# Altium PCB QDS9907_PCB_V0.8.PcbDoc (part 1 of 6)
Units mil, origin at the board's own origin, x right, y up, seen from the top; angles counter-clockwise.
Board outline 3410.03 x 4010.03 mil, 8 copper layers (Top Layer, GND1, INT1, INT2, PWR1, GND2, GND3, Bottom Layer), stack 81.668 mil thick; 250 components, 129 nets, 7010 pads, 701 vias.
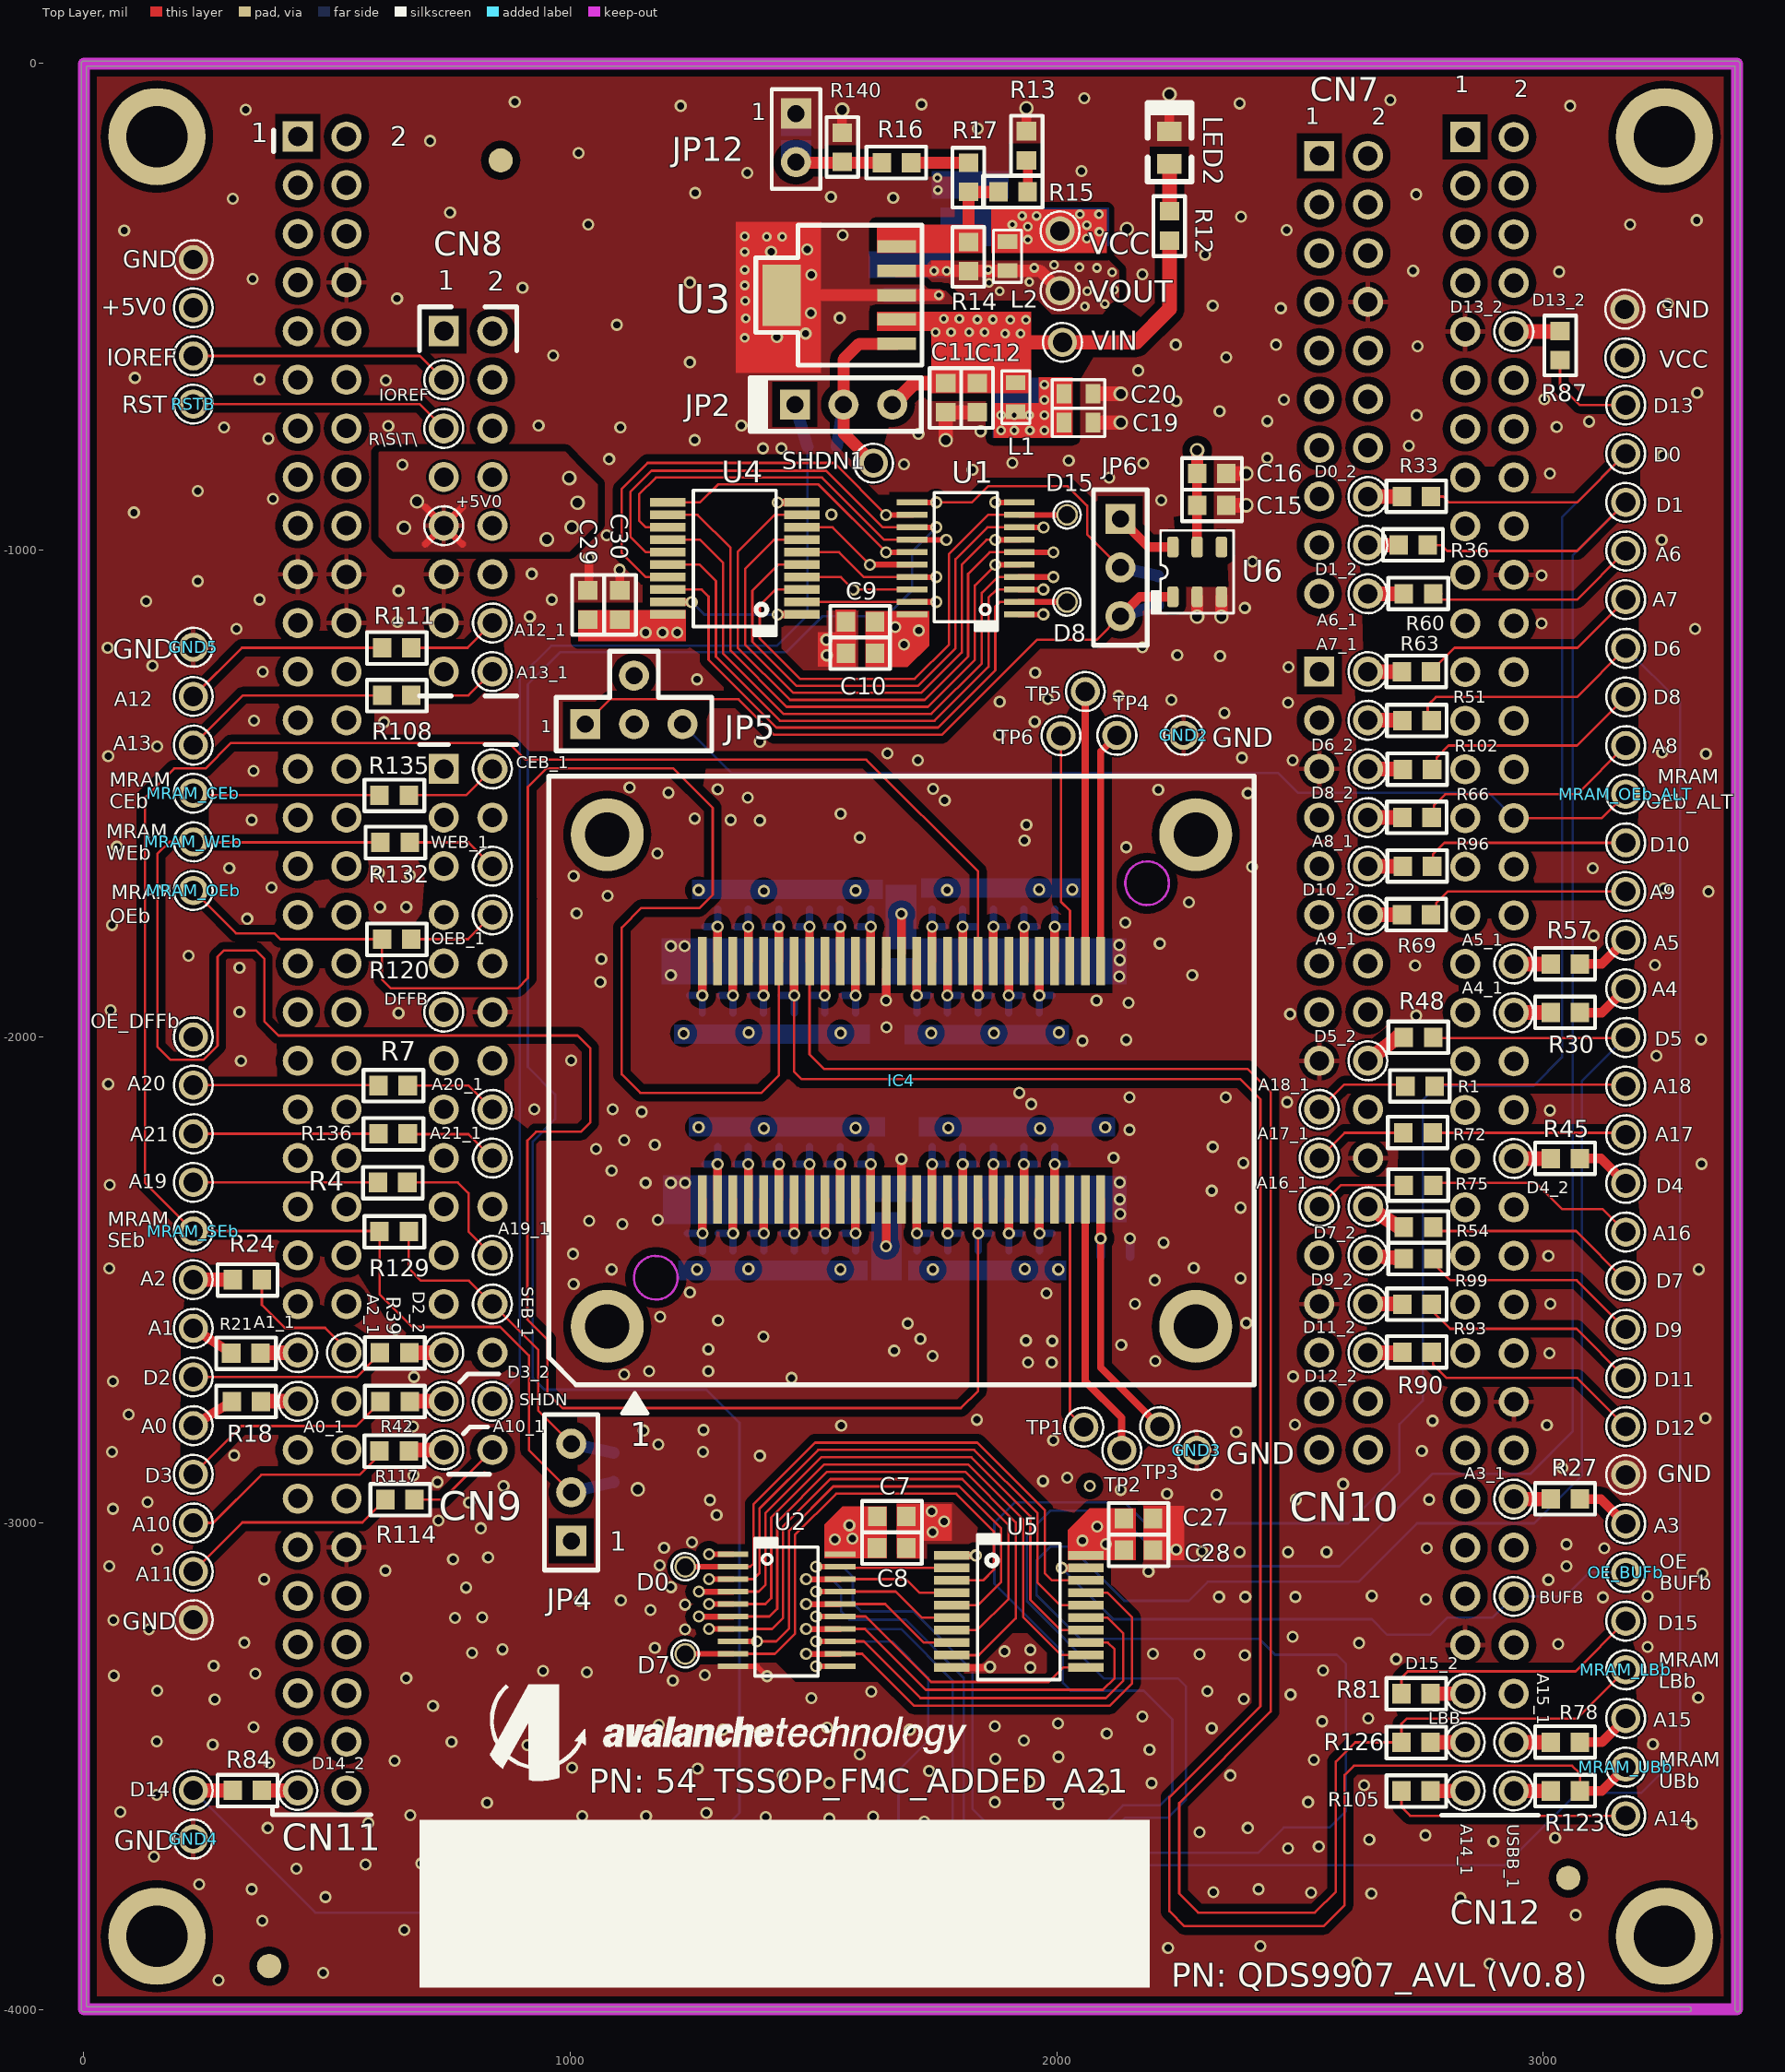
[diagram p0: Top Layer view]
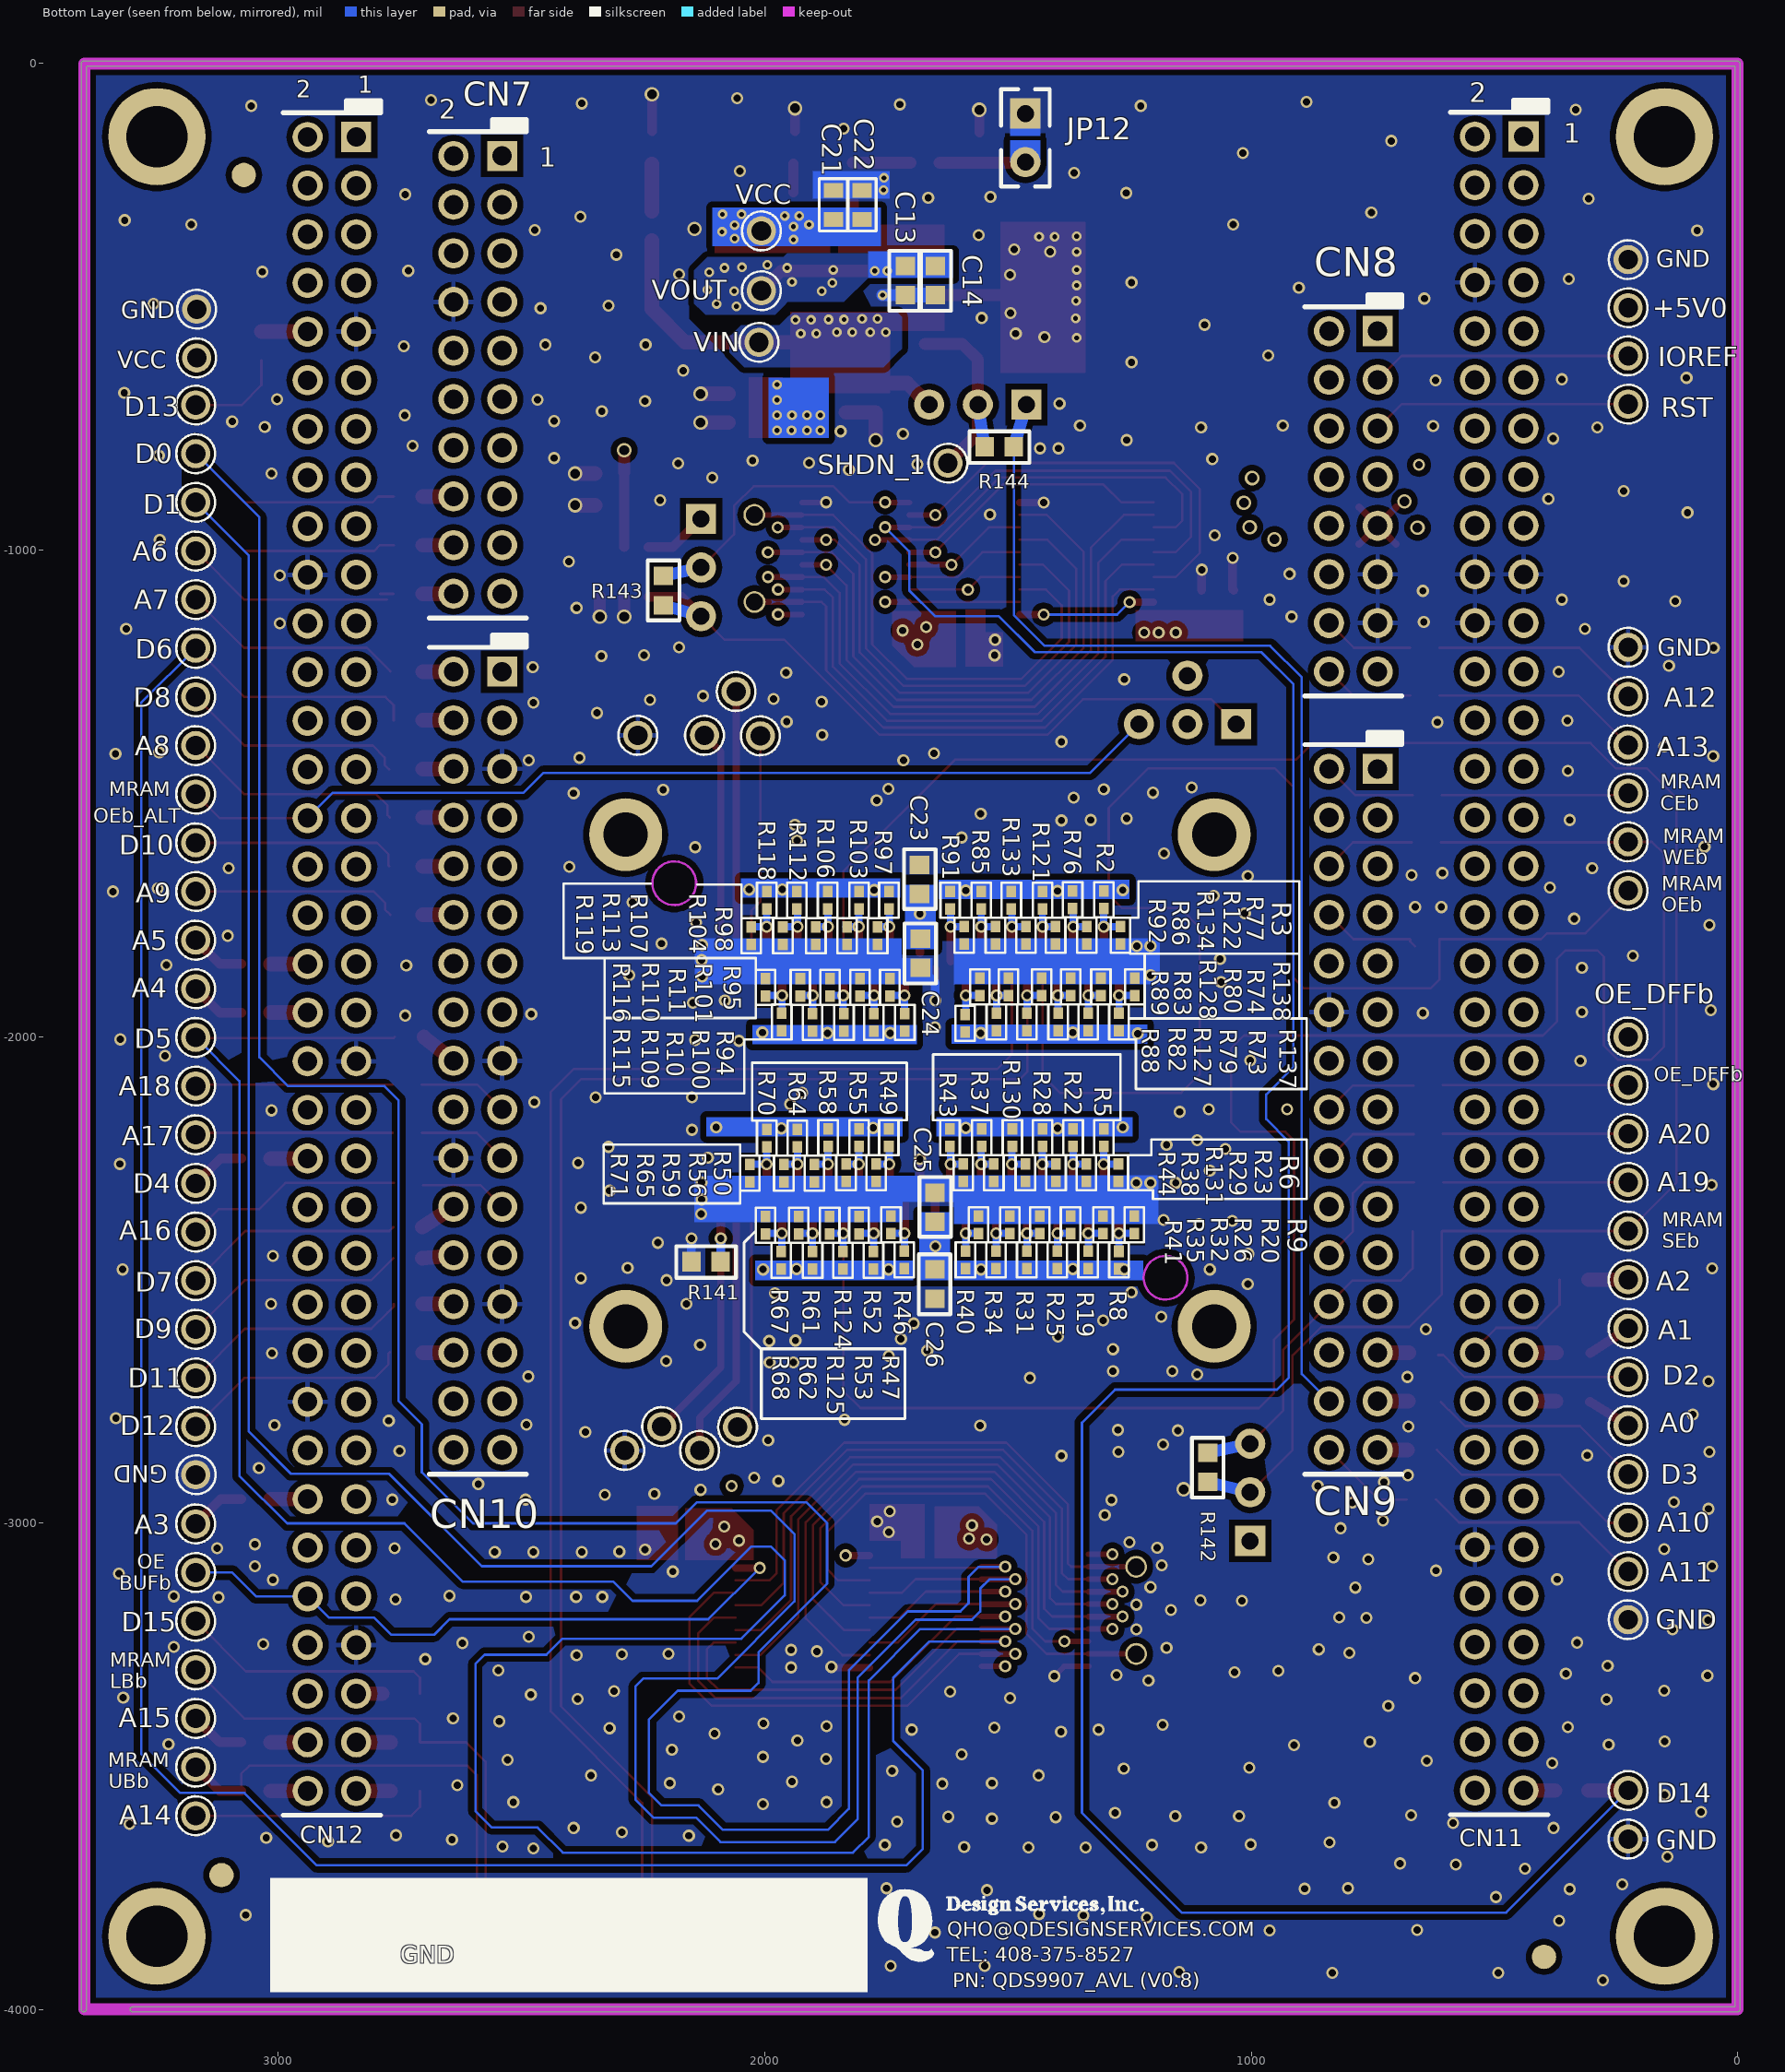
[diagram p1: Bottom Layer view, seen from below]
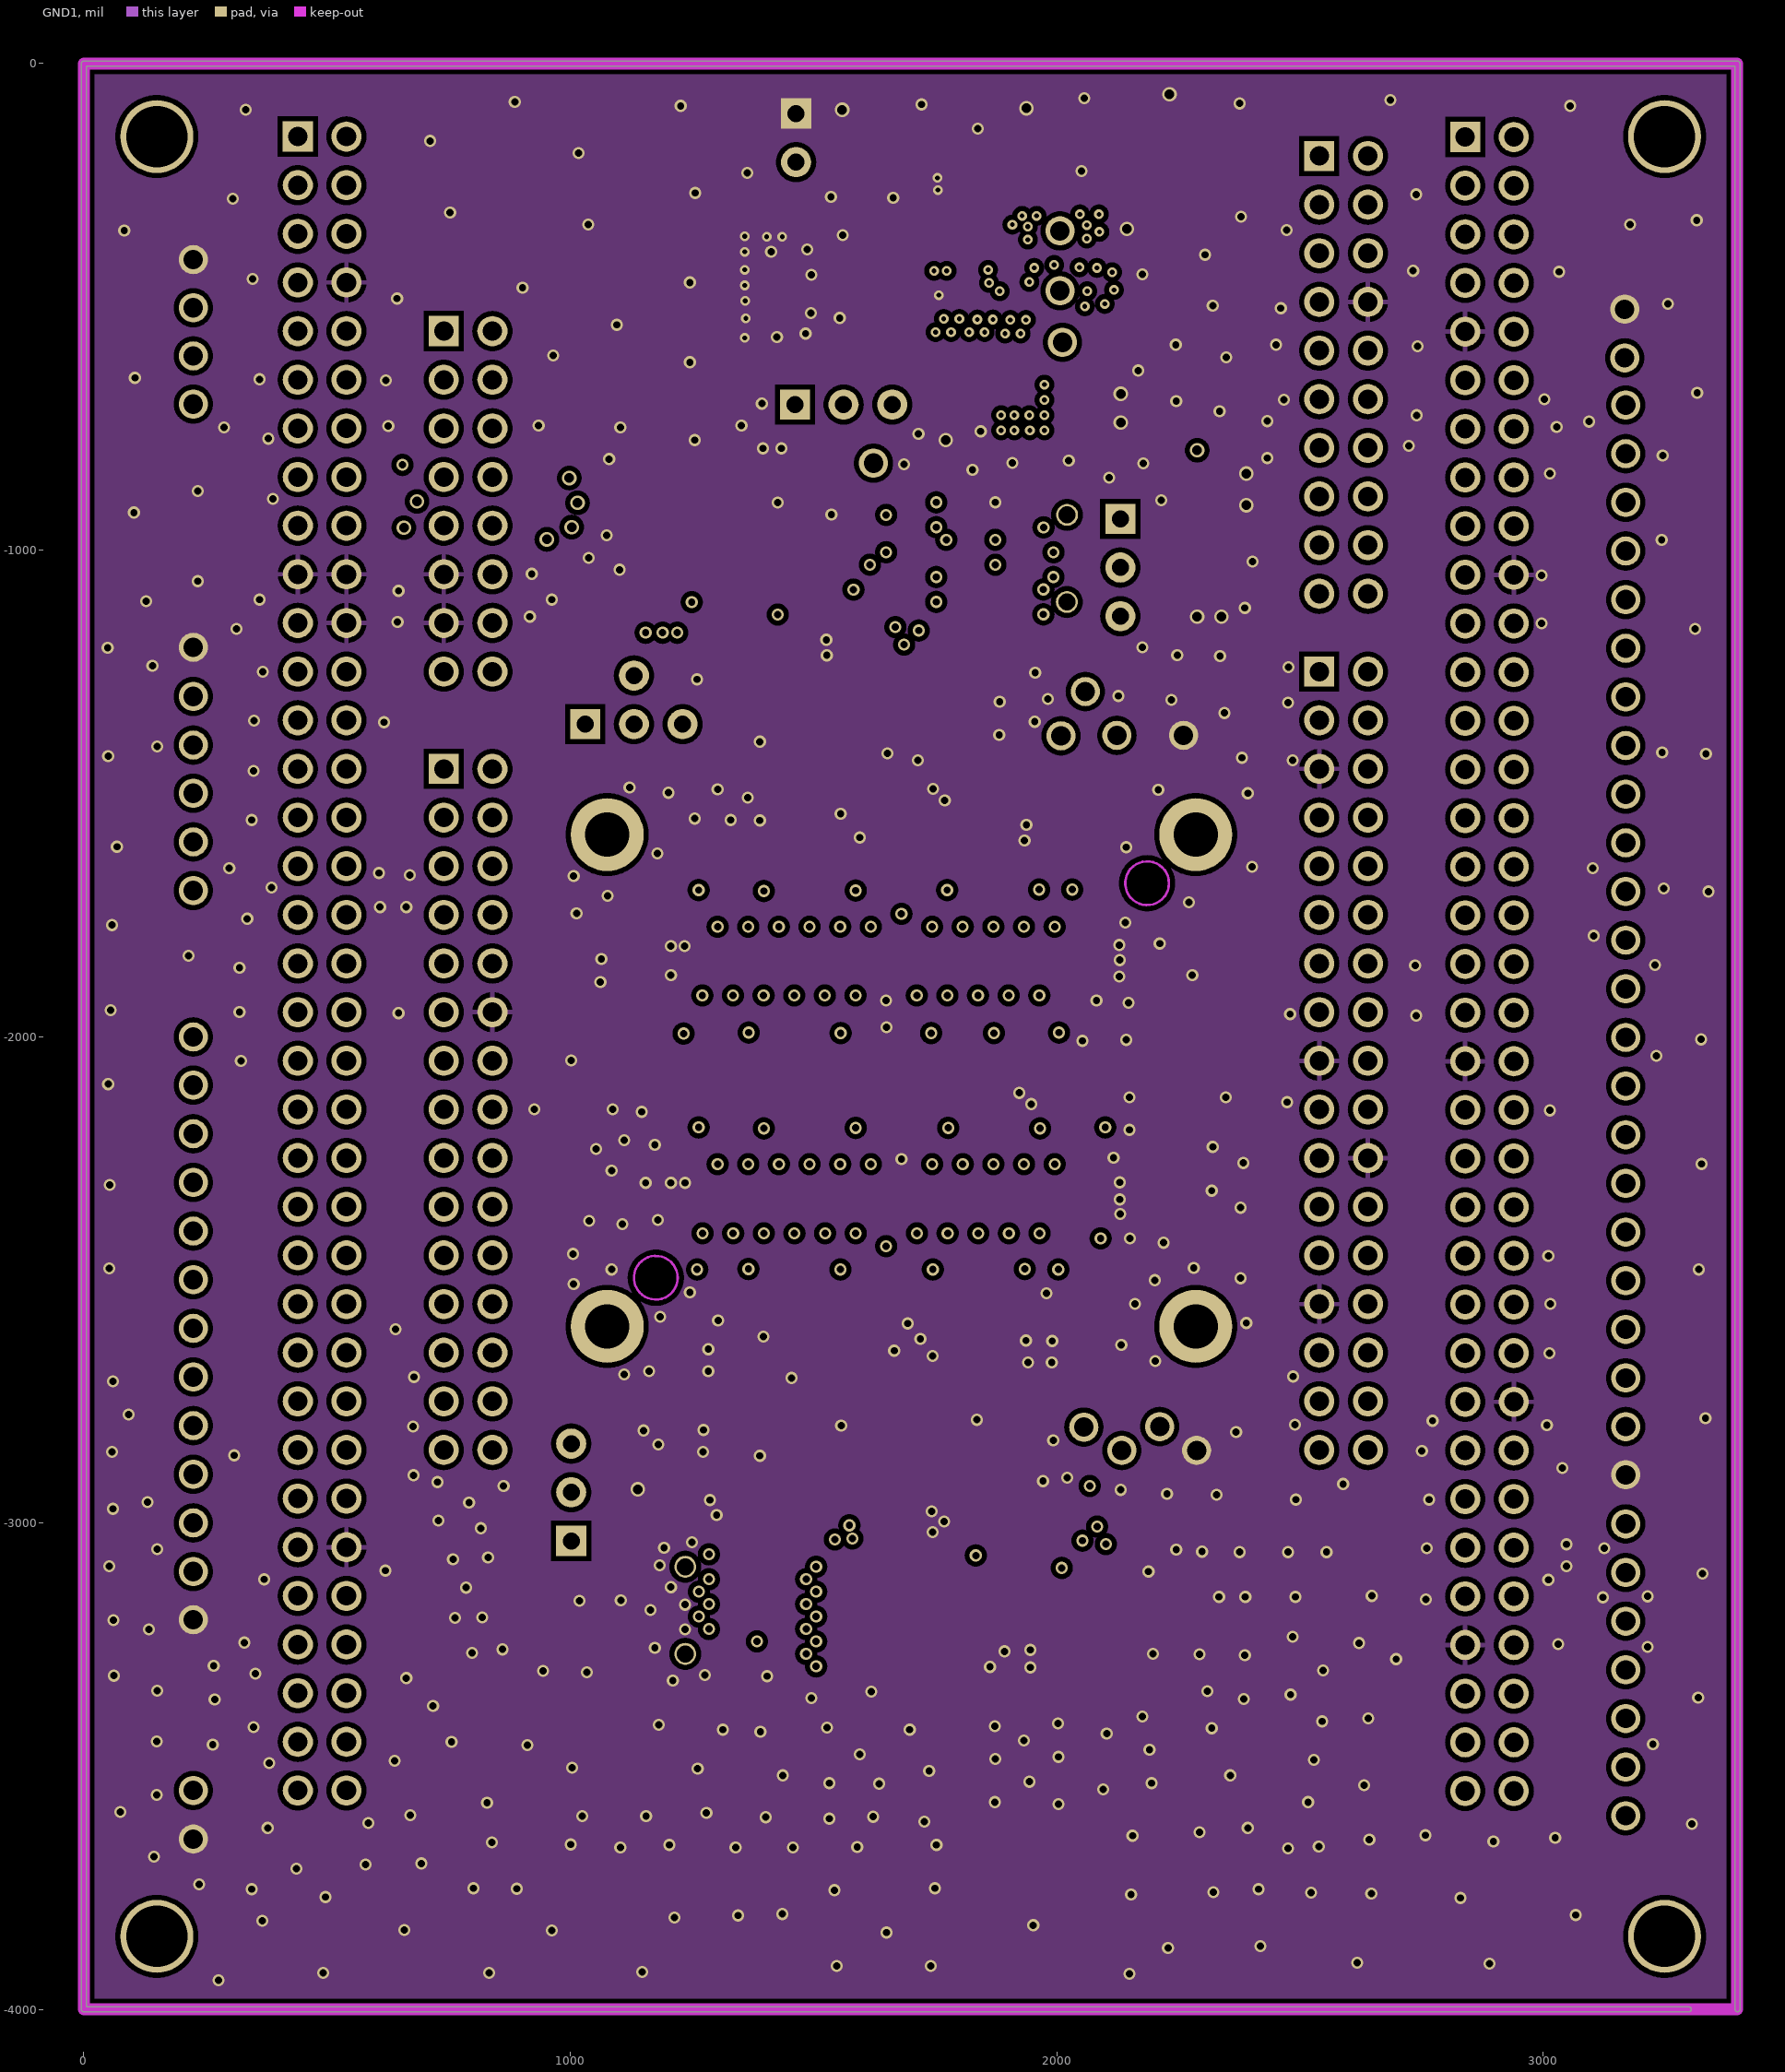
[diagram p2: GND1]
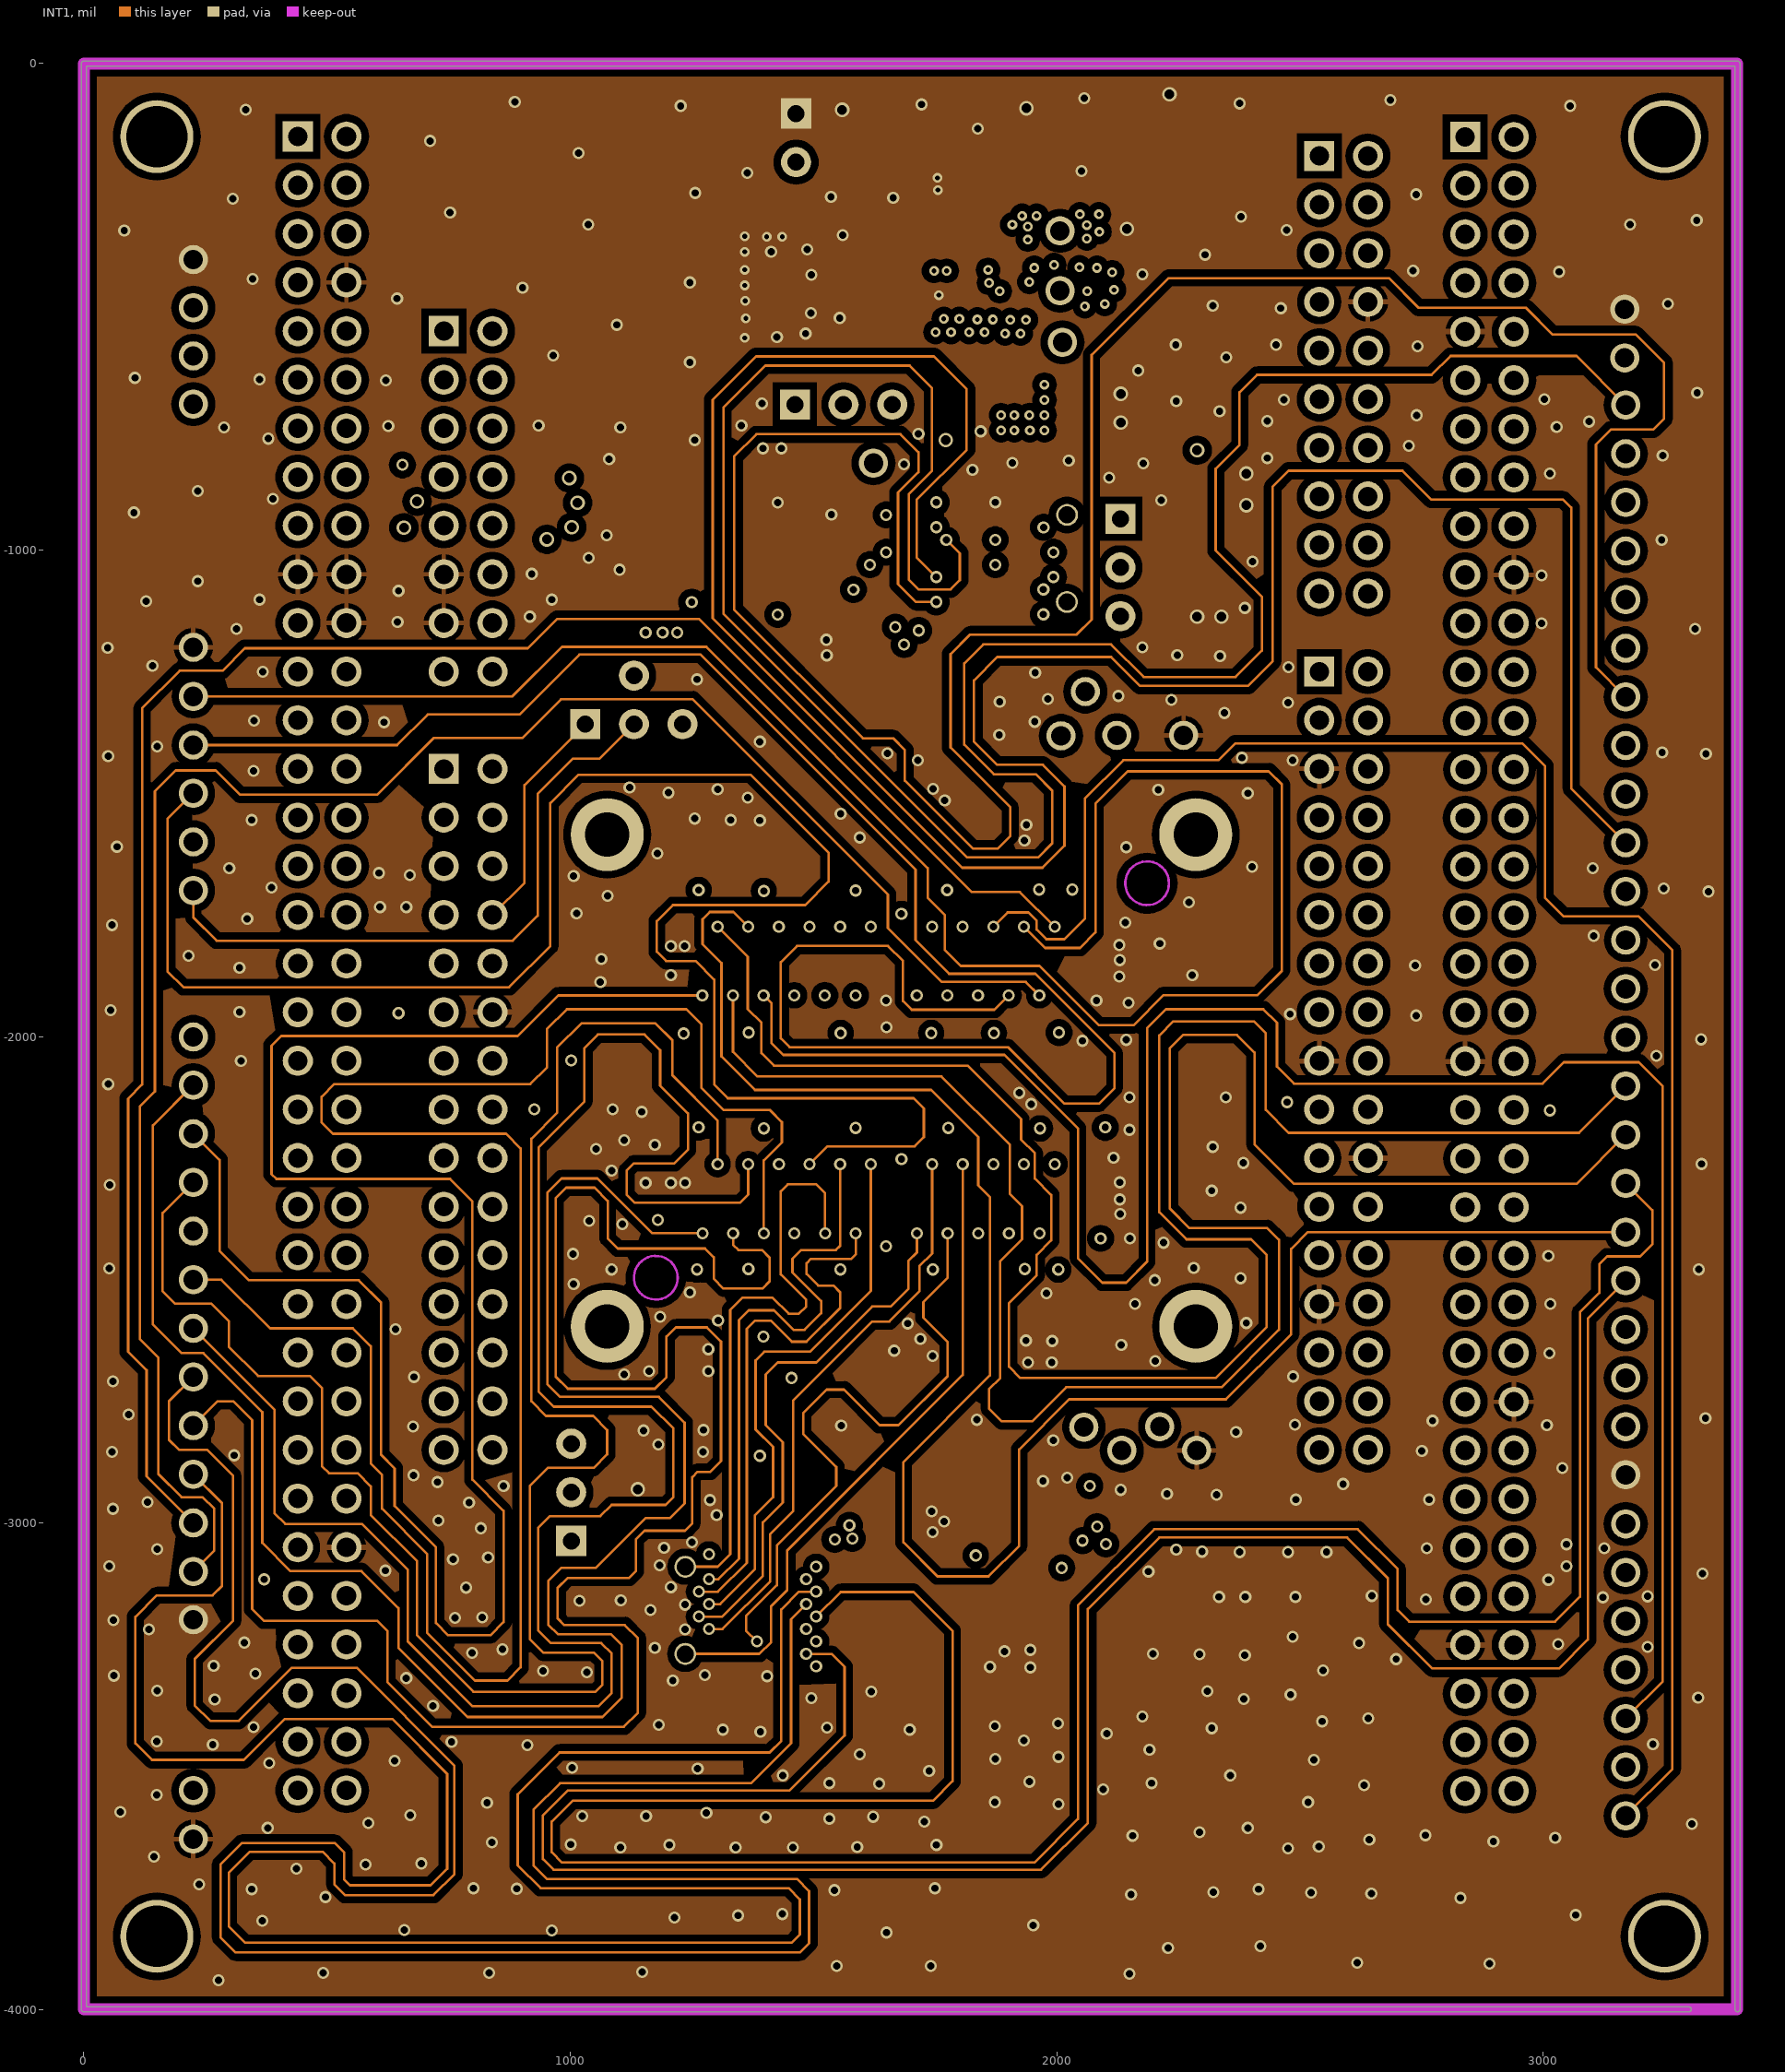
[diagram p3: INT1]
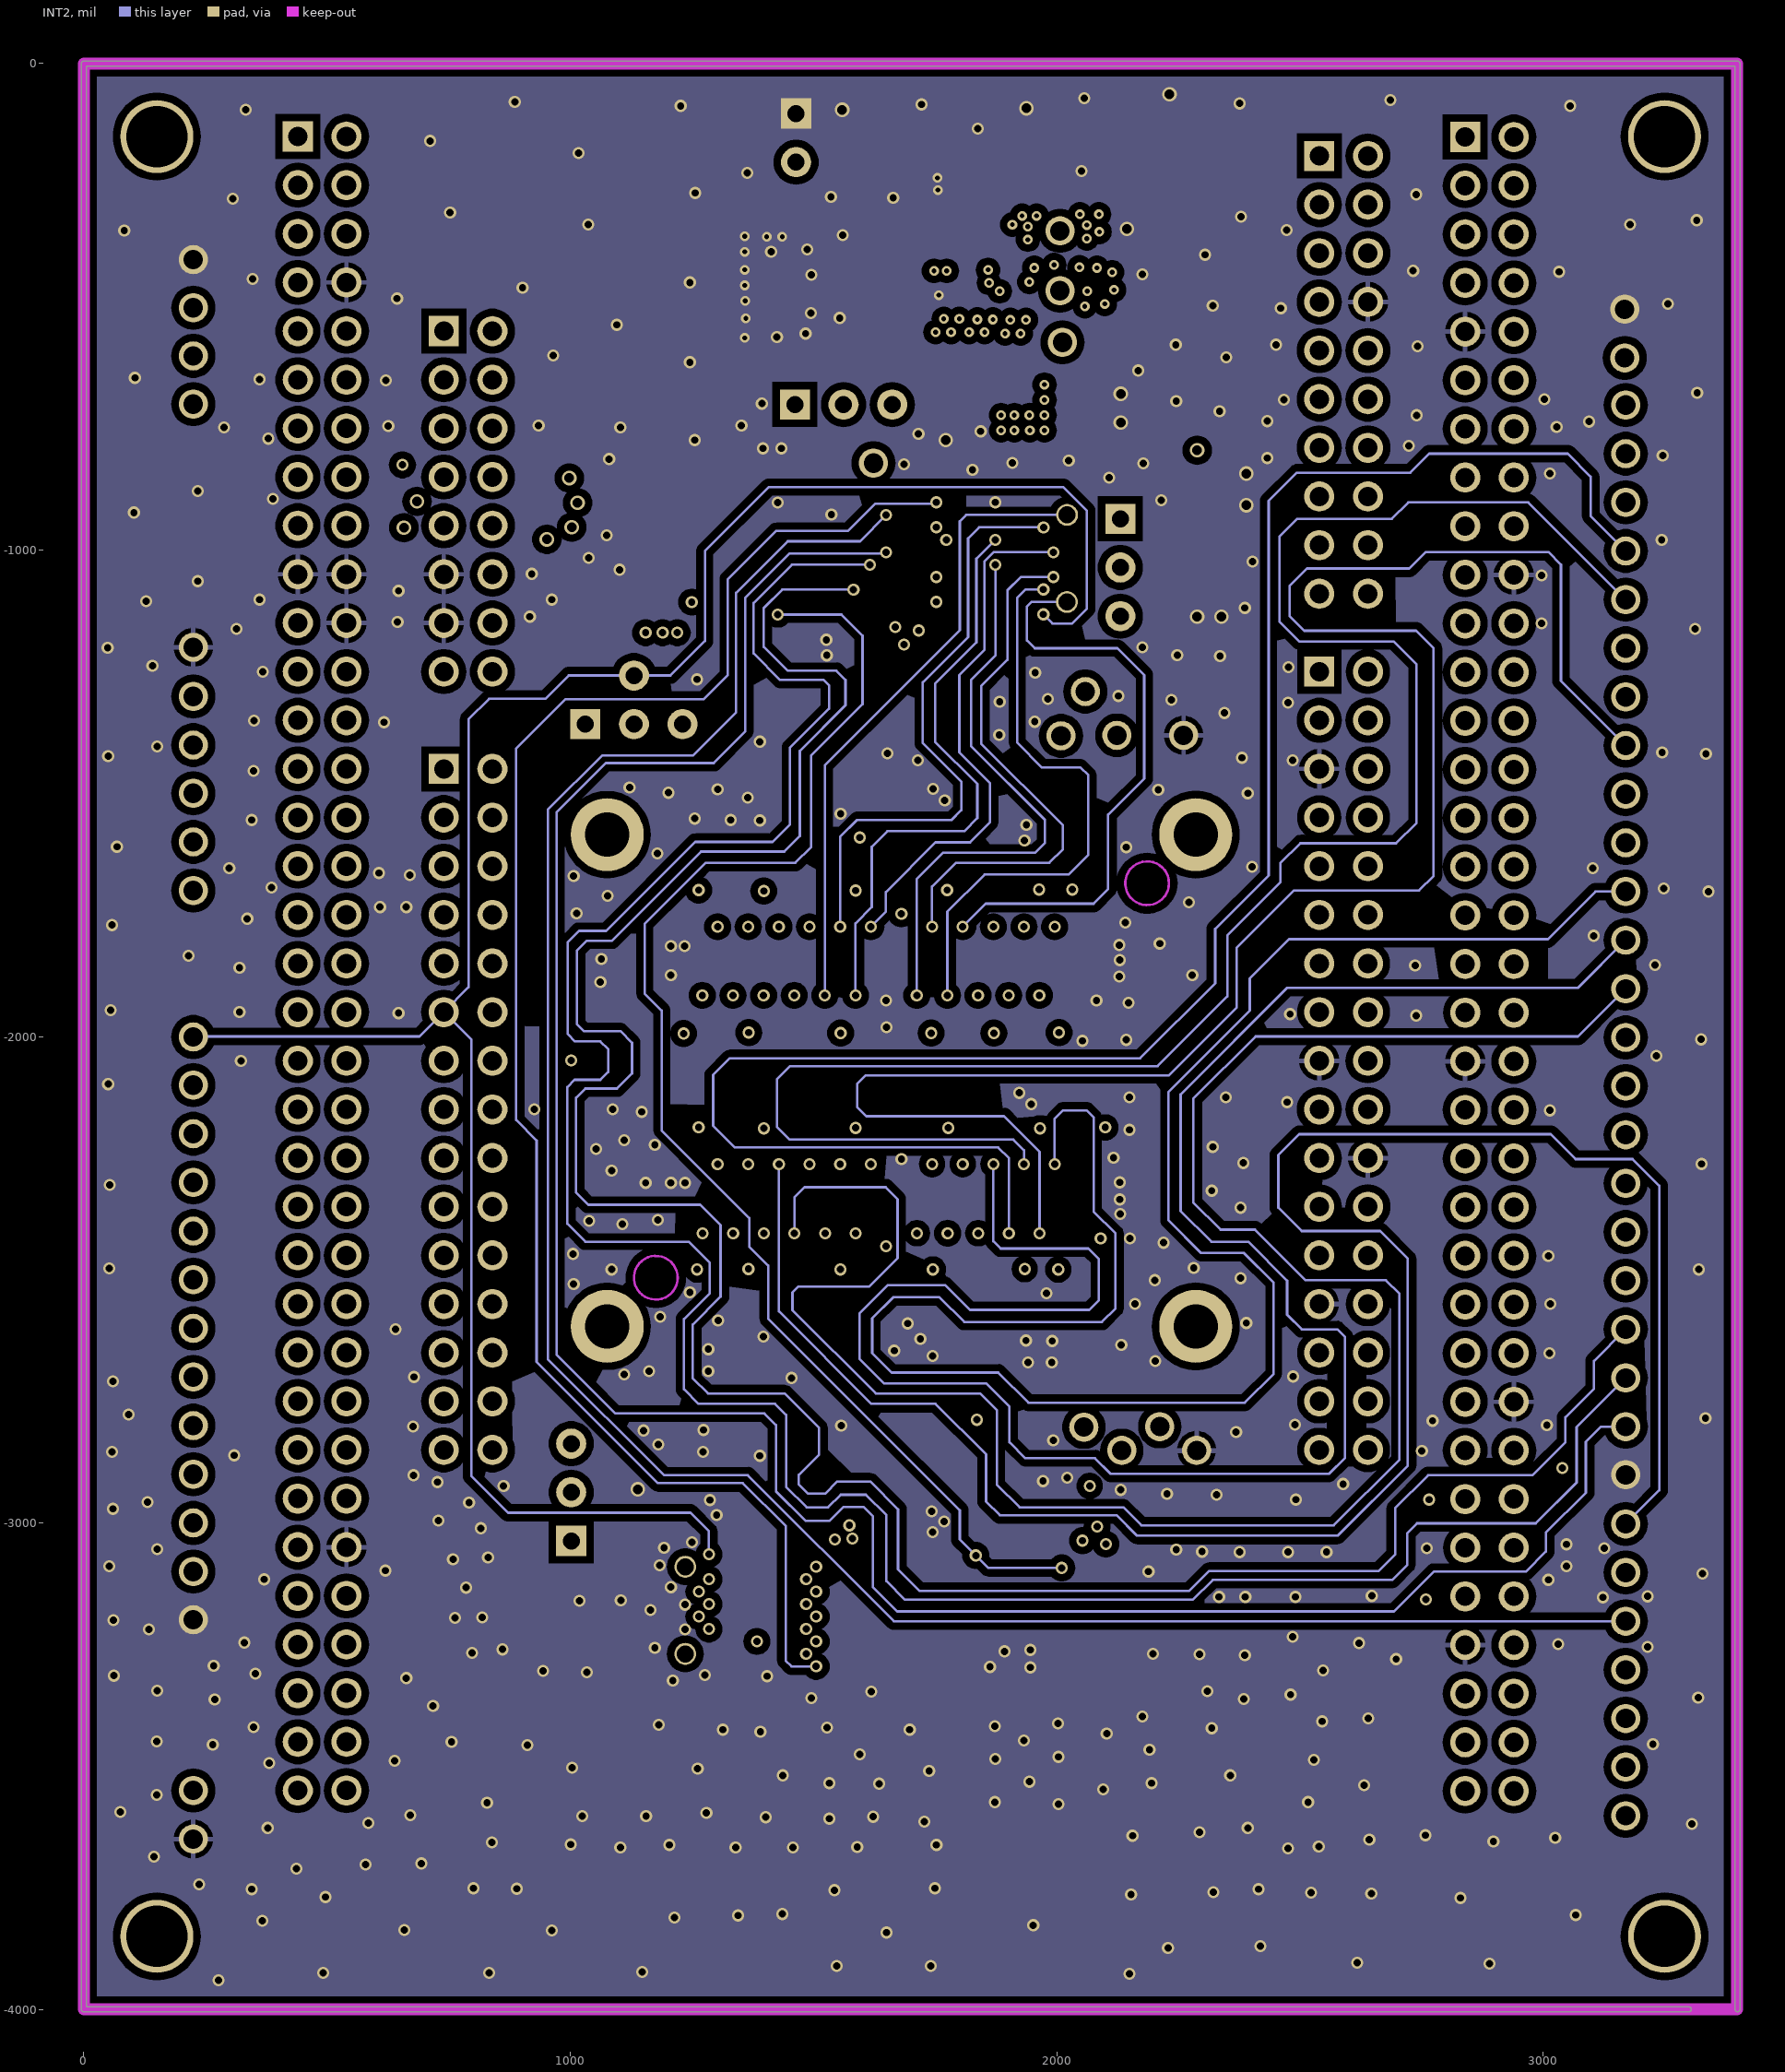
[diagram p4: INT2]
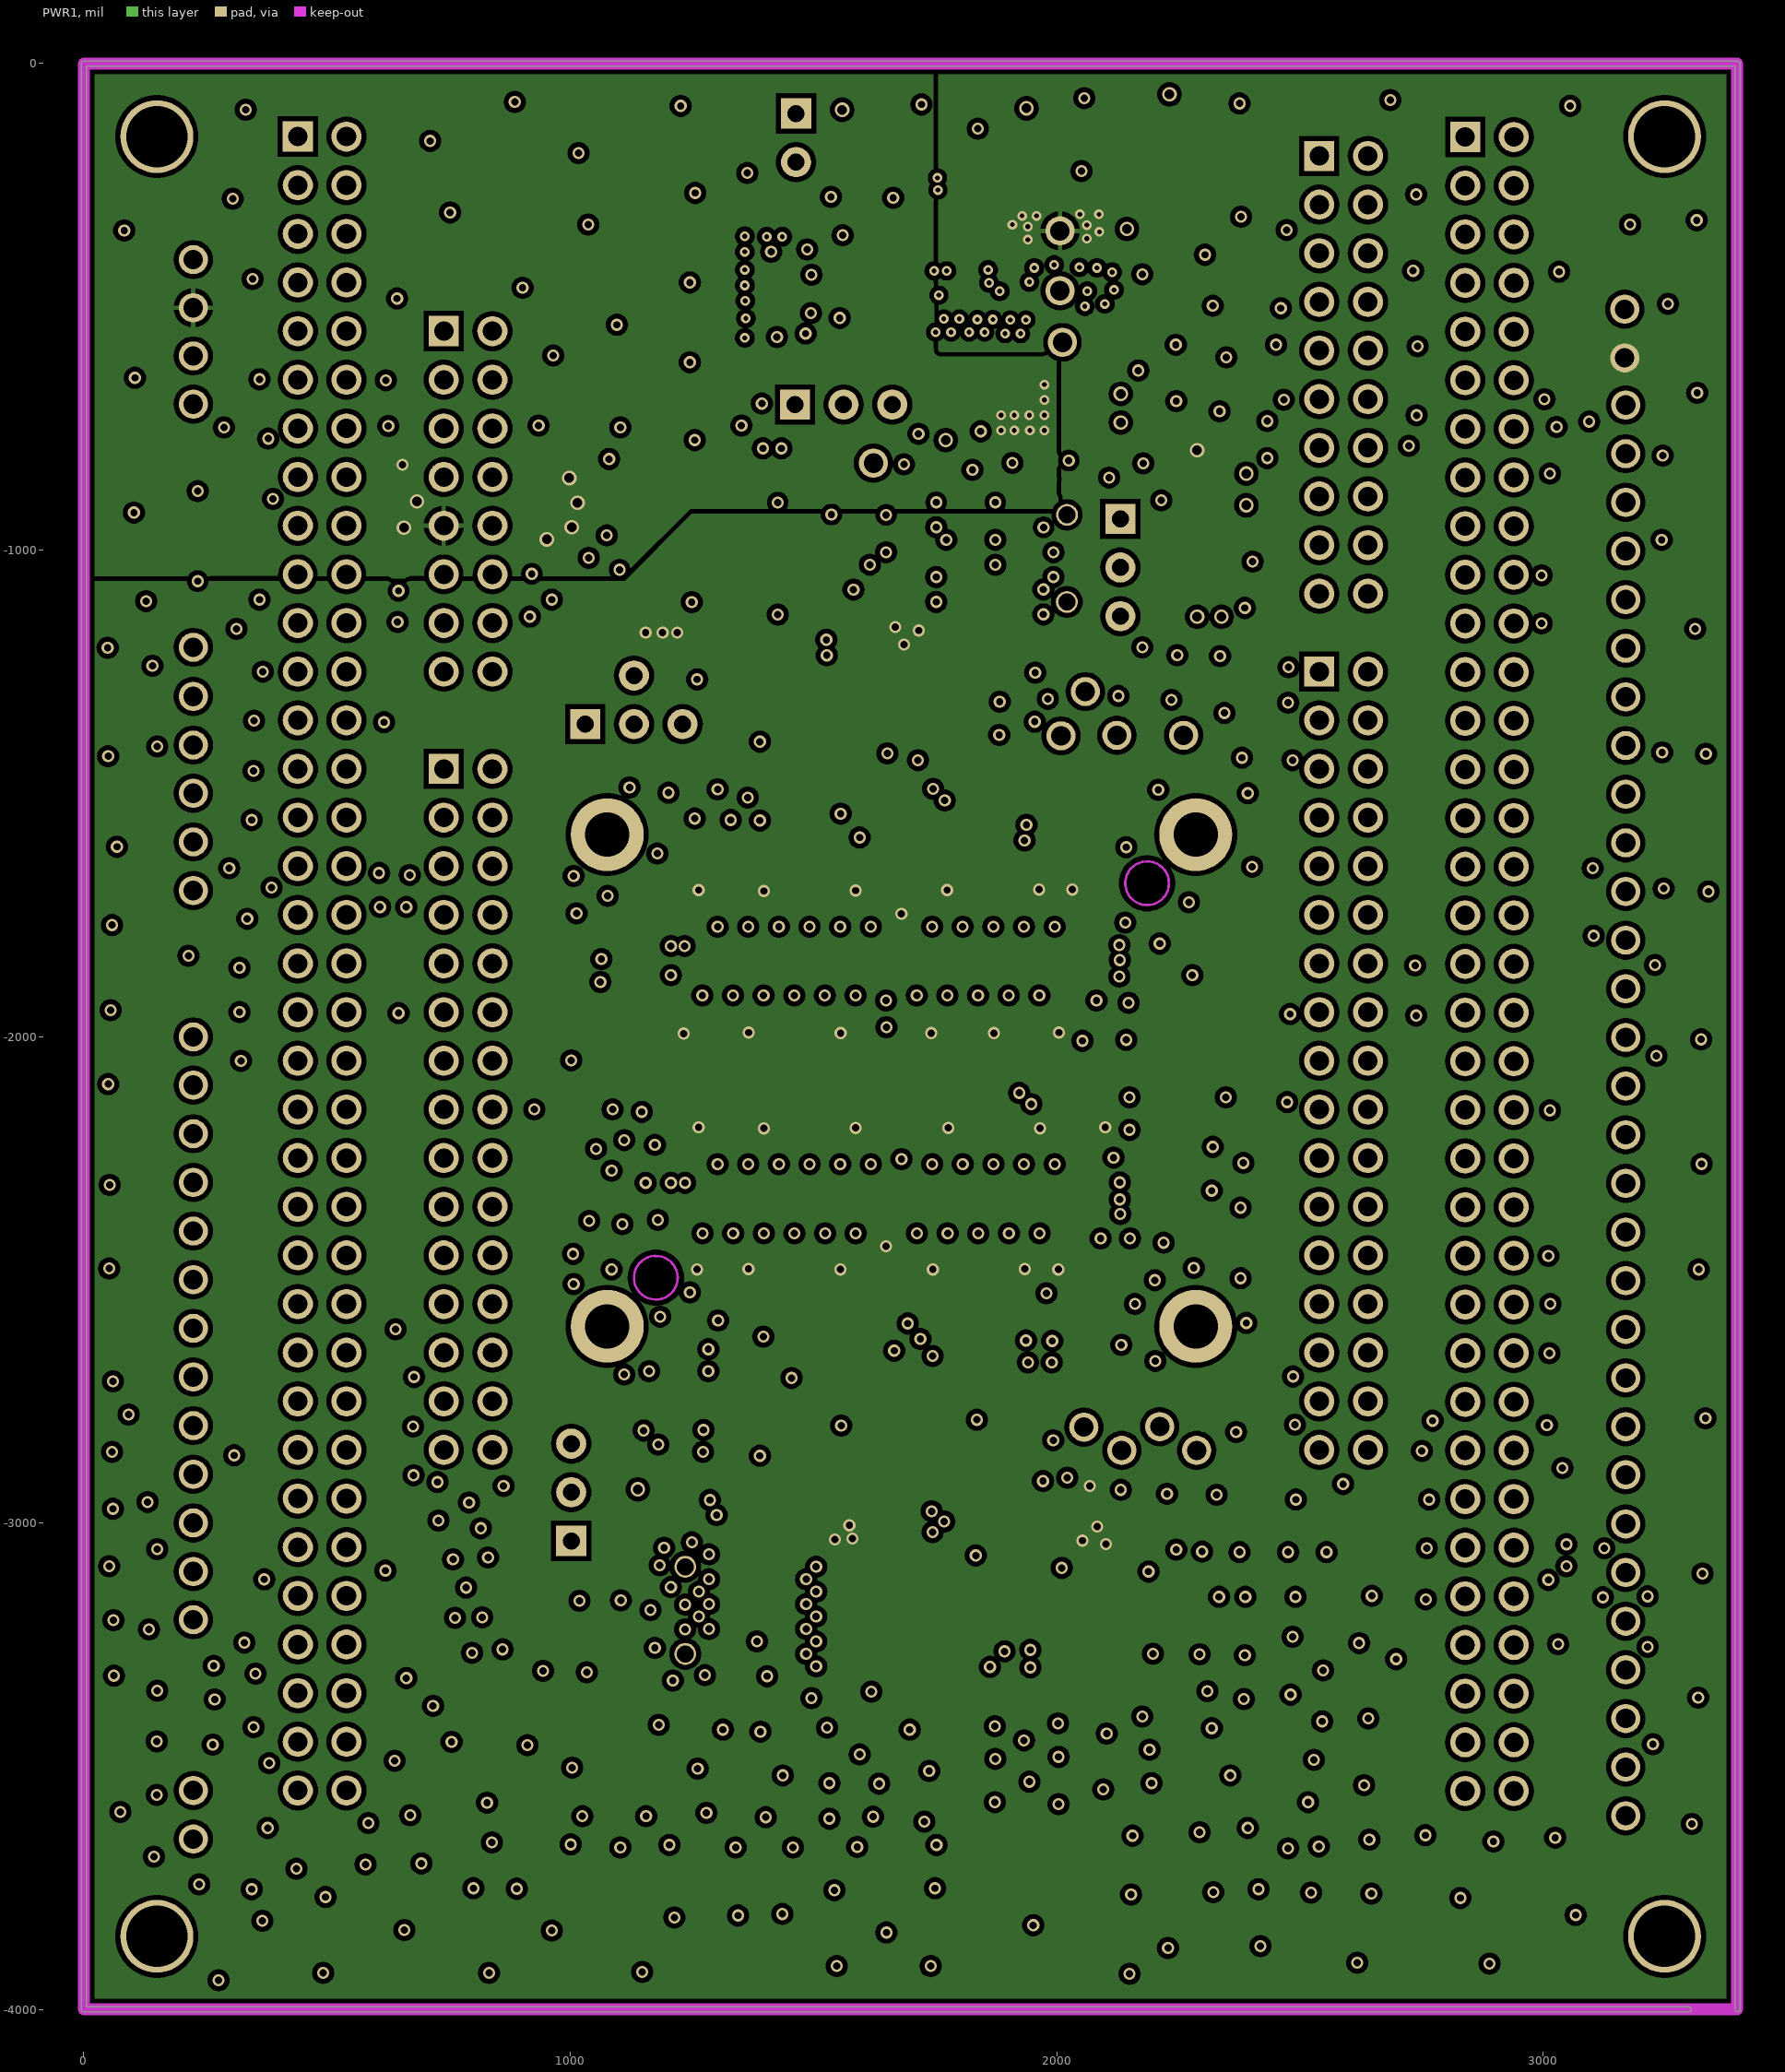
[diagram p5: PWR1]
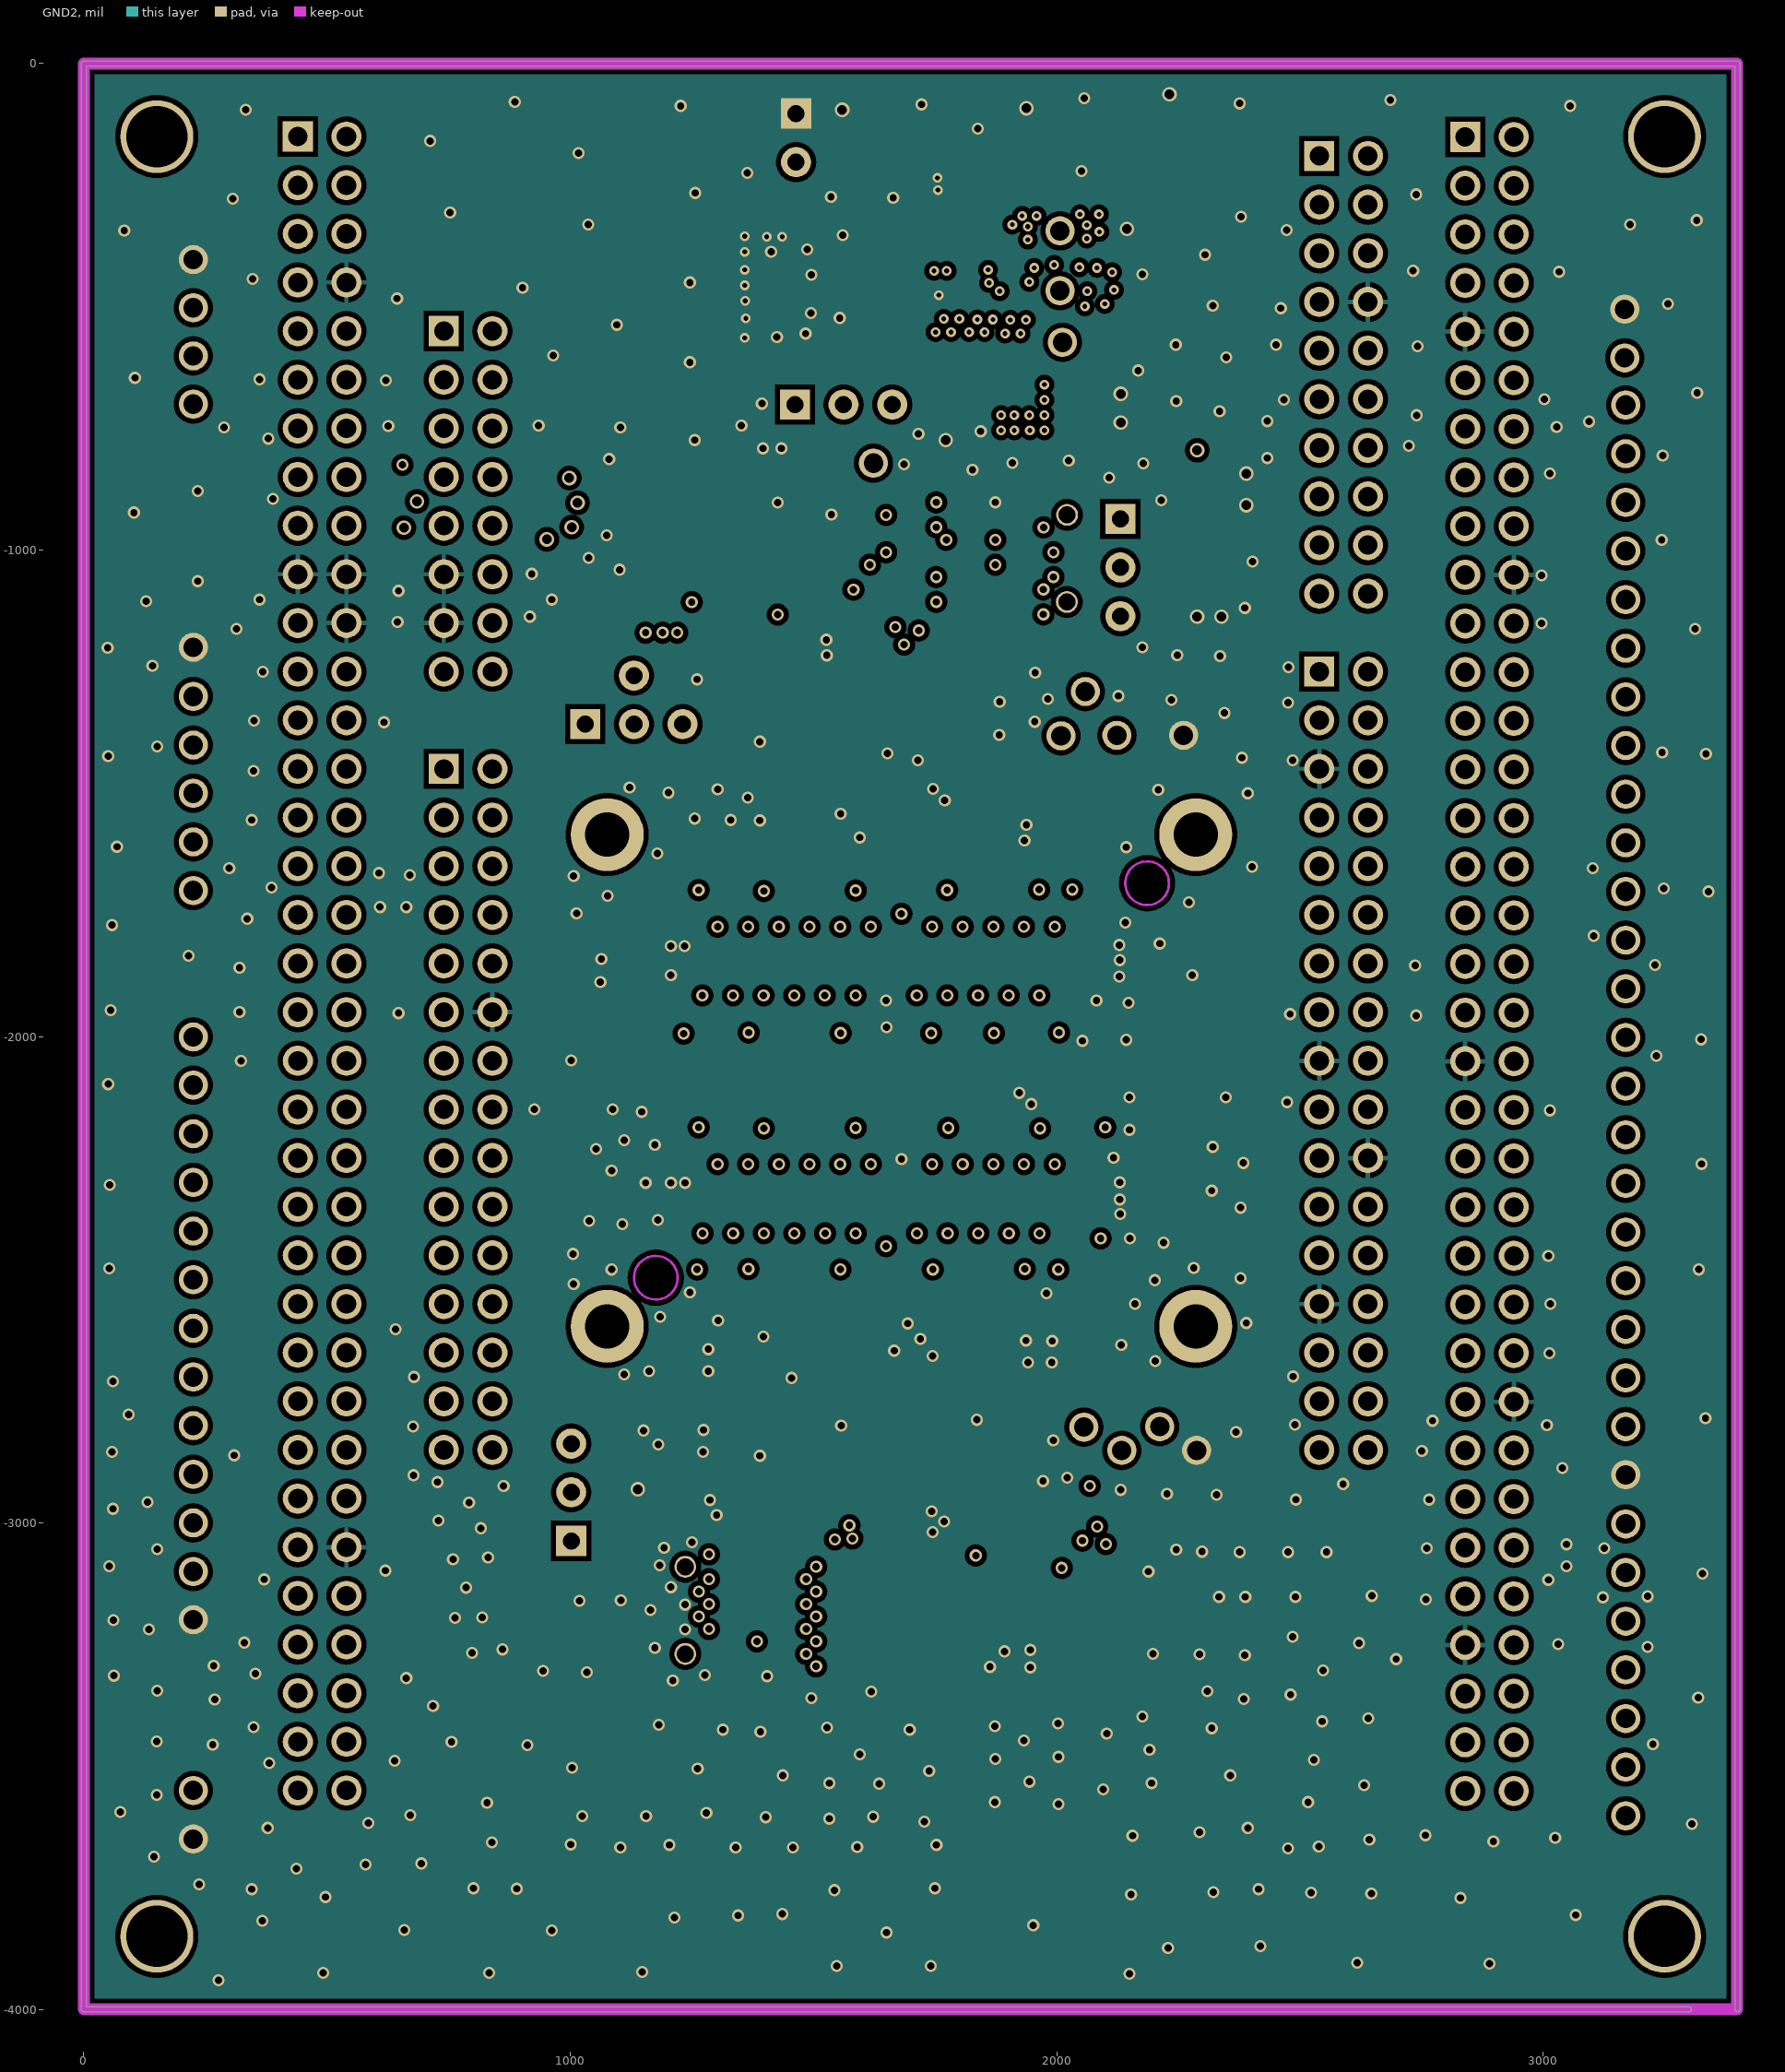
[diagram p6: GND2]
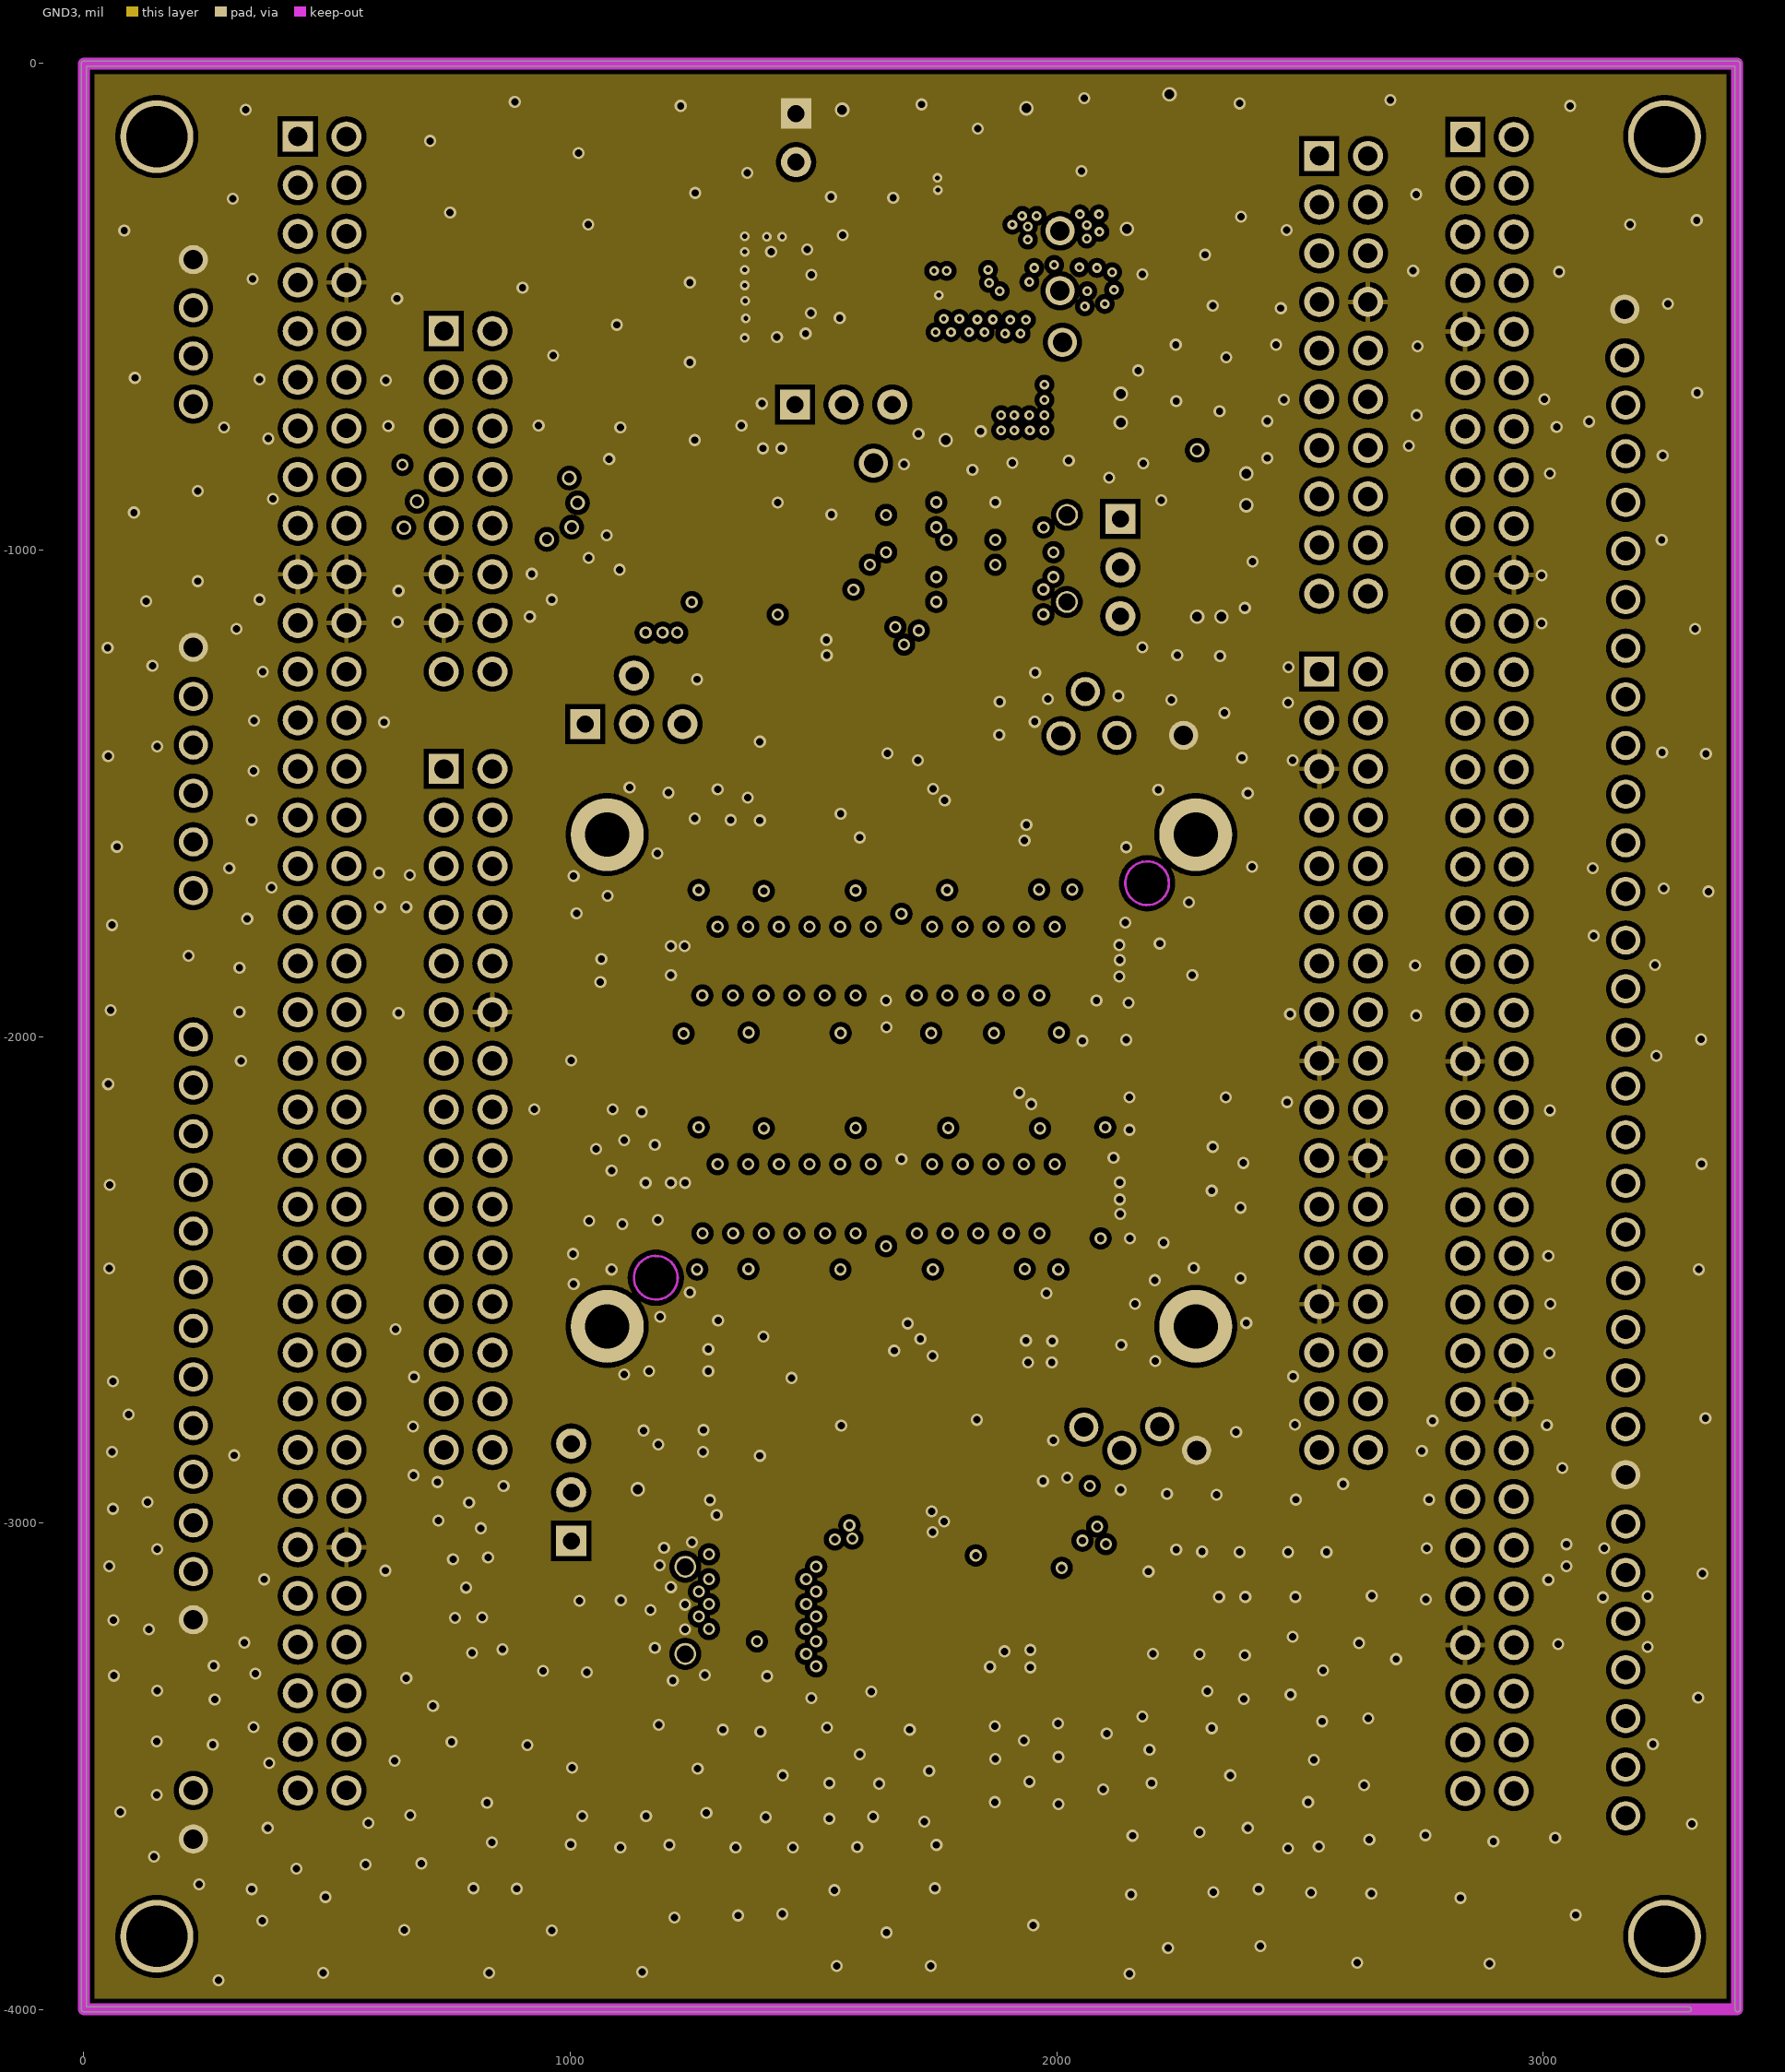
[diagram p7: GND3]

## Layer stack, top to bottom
Top Solder: solder mask 1, Solder Resist, Dk 3.5
Top Layer: signal copper 6
Dielectric1: core 15, FR-4, Dk 4.2
GND1: signal copper 2
Dielectric 8: prepreg 5, Dk 4.2
INT1: signal copper 1.417
Dielectric 10: core 10, Dk 4.2
INT2: signal copper 1.417
Dielectric 12: prepreg 5, Dk 4.2
PWR1: signal copper 2
Dielectric 11: core 10, Dk 4.2
GND2: signal copper 1.417
Dielectric 13: prepreg 5, Dk 4.2
GND3: signal copper 1.417
Dielectric 7: core 10, Dk 4.2
Bottom Layer: signal copper 6
Bottom Solder: solder mask 1, Solder Resist, Dk 3.5

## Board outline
-5.01,-4000 -5.01,-3999.97 ccw(c0,-4000) -4.92,-4000.98 ccw(c0,-4000) 0.07,-4005.01 3300,-4005.01 ccw(c3300,-4000) 3305.02,-4000 ccw(c3300,-4000) 3300,-3994.98 5.02,-3994.98 5.01,-5.02 3394.98,-5.02 3394.98,-4000 ccw(c3400,-4000) 3405.01,-4000 3405.01,0 cw(c3400,0) 3405.01,0 ccw(c3400,0) 3400,5.01 0.09,5.01 ccw(c0,0) -5.02,0

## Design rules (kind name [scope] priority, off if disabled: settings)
Clearance [All] p1: gap=10
ComponentClearance [All] p1 off: gap=10 collisioncheckmode=3 verticalgap=10 showdistances=FALSE
FabricationTestPointUsage TestPointUsage [All] p1: valid=0 allowmultiple=FALSE
FabricationTestpoint Testpoint [(IsPad And (OnTopLayer Or OnBottomLayer))] p1: side=3 testpointundercomponent=TRUE minsize=40 maxsize=100 preferedsize=60 minholesize=0 maxholesize=40 preferedholesize=32 testpointgrid=1 allowsidetop=TRUE allowsidebottom=TRUE usegrid=TRUE gridtolerance=0.01
Height [All] p1 off: minheight=0 maxheight=1000 prefheight=500
HoleSize [All] p1 off: absolutevalues=TRUE maxlimit=100 minlimit=1 maxpercent=80.000 minpercent=20.000
PlaneConnect [All] p1: planeconnectstyle=Relief reliefexpansion=25 reliefentries=4 reliefconductorwidth=10 reliefairgap=12
PolygonConnect [All] p1: connectstyle=Direct reliefconductorwidth=10 reliefentries=4 polygonreliefangle="90 Angle" airgapwidth=10
RoomDefinition PG01_ST_PARALLEL_X16_FMC_3V_TSSOP_REV2.0_V0.3 [InComponentClass('PG01_ST_PARALLEL_X16_FMC_3V_TSSOP_REV2.0_V0.3')] p1: confinementstyle=ConfineIn formatcopy=TRUE lockcomponents=FALSE outline 4298.7,232.29 4554,232.29 4554,472.29 4298.7,472.29
RoomDefinition PG02_ST_PARALLEL_X16_FMC_3V_TSSOP_REV2.0_V0.3 [InComponentClass('PG02_ST_PARALLEL_X16_FMC_3V_TSSOP_REV2.0_V0.3')] p2 off: confinementstyle=ConfineIn formatcopy=TRUE lockcomponents=FALSE outline 1109.7,514 1259,514 1259,738 1109.7,738
RoutingVias [All] p1: holewidth=20 width=40 viastyle="Through Hole" minholewidth=20 minwidth=40 maxholewidth=20 maxwidth=40
ShortCircuit [InNet('NetA401_1') vs InNet('GND')] p1: allowed=FALSE
SolderMaskExpansion [All] p1: expansion=0
UnpouredPolygon [All] p1: allowunpoured=FALSE
Width Width_1 [All] p1: maxlimit=100 minlimit=4 preferedwidth=5
22 further rules are at their usual default settings.

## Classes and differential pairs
component class PG01_ST_PARALLEL_X16_FMC_3V_TSSOP_REV2.0_V0.3: +5V0 A0 A1 A2 A3 A4 A5 A6 A7 A8 A9 A10 A11 A12 A13 A14 A15 A16 A17 A18 A19 A20 A21 C7 C8 C9 C10 C11 C12 C13 C14 C15 C16 C19 C20 C21 C22 C23 C24 C25 C26 C27 C28 C29 C30 CN7 CN8 CN9 CN10 CN11 CN12 D0 D1 D2 D3 D4 D5 D6 D7 D8 D9 D10 D11 D12 D13 D14 D15 GND2 GND3 GND4 GND5 IC4 IOREF JP2 JP4 JP5 JP6 JP12 L1 L2 LED2 MRAM_CEb MRAM_LBb MRAM_OEb MRAM_OEb_ALT MRAM_SEb MRAM_UBb MRAM_WEb OE_BUFb OE_DFFb R12 R13 R14 R15 R16 R17 R140 R141 R142 R143 R144 RSTB SHDN1 TP1 TP2 TP3 TP4 TP5 TP6 U1 U2 U3 U4 U5 U6 VCC VIN VOUT
component class PG02_ST_PARALLEL_X16_FMC_3V_TSSOP_REV2.0_V0.3: R1 R2 R3 R4 R5 R6 R7 R8 R9 R10 R11 R18 R19 R20 R21 R22 R23 R24 R25 R26 R27 R28 R29 R30 R31 R32 R33 R34 R35 R36 R37 R38 R39 R40 R41 R42 R43 R44 R45 R46 R47 R48 R49 R50 R51 R52 R53 R54 R55 R56 R57 R58 R59 R60 R61 R62 R63 R64 R65 R66 R67 R68 R69 R70 R71 R72 R73 R74 R75 R76 R77 R78 R79 R80 R81 R82 R83 R84 R85 R86 R87 R88 R89 R90 R91 R92 R93 R94 R95 R96 R97 R98 R99 R100 R101 R102 R103 R104 R105 R106 R107 R108 R109 R110 R111 R112 R113 R114 R115 R116 R117 R118 R119 R120 R121 R122 R123 R124 R125 R126 R127 R128 R129 R130 R131 R132 R133 R134 R135 R136 R137 R138
net class match_D: D0 D1 D2 D3 D4 D5 D6 D7 D8 D9 D10 D11 D12 D13 D14 D15
net class match_D_1: D0_1 D1_1 D2_1 D3_1 D4_1 D5_1 D6_1 D7_1 D8_1 D9_1 D10_1 D11_1 D12_1 D13_1 D14_1 D15_1
net class match_MRAM: MRAM_CEB MRAM_LBB MRAM_OE MRAM_OEB MRAM_SEB MRAM_UBB MRAM_WEB
net class match_A: A0 A1 A2 A3 A4 A5 A6 A7 A8 A9 A10 A11 A12 A13 A14 A15 A16 A17 A18 A19 A20 A21
component class thermal: +5V0 CN7 CN8 CN9 CN10 CN11 CN12 GND2 GND3 GND4 GND5 VCC VIN VOUT

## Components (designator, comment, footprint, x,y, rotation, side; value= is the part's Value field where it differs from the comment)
+5V0 "TP" "TEST POINT" 225,-502 r90 top locked
A0 "TP" "TEST POINT" 225,-2800 r90 top locked
A1 "TP" "TEST POINT" 225,-2600 r0 top locked
A2 "TP" "TEST POINT" 225,-2500 r90 top locked
A3 "TP" "TEST POINT" 3170,-3002 r90 top locked
A4 "TP" "TEST POINT" 3170,-1902 r90 top locked
A5 "TP" "TEST POINT" 3170,-1802 r90 top locked
A6 "TP" "TEST POINT" 3170,-1002 r0 top locked
A7 "TP" "TEST POINT" 3170,-1102 r0 top locked
A8 "TP" "TEST POINT" 3170,-1402 r0 top locked
A9 "TP" "TEST POINT" 3170,-1702 r0 top locked
A10 "TP" "TEST POINT" 225,-3000 r0 top locked
A11 "TP" "TEST POINT" 225,-3100 r0 top locked
A12 "TP" "TEST POINT" 225,-1301 r0 top locked
A13 "TP" "TEST POINT" 225,-1401 r0 top locked
A14 "TP" "TEST POINT" 3170,-3602 r0 top locked
A15 "TP" "TEST POINT" 3170,-3402 r0 top locked
A16 "TP" "TEST POINT" 3170,-2402 r90 top locked
A17 "TP" "TEST POINT" 3170,-2202 r90 top locked
A18 "TP" "TEST POINT" 3170,-2102 r90 top locked
A19 "TP" "TEST POINT" 225,-2300 r90 top locked
A20 "TP" "TEST POINT" 225,-2100 r0 top locked
A21 "TP" "TEST POINT" 225,-2200 r0 top locked
C7 "10nF" N_0603 1661,-2987 r0 top locked
C8 "1uF" N_0603 1660.81,-3051.5 r0 top locked
C9 "10nF" N_0603 1596.5,-1147.5 r180 top locked
C10 "1uF" N_0603 1596.5,-1212.5 r180 top locked
C11 "10nF" N_0603 1772,-687 r270 top locked
C12 "4.7uF" N_0603 1837,-687 r270 top locked
C13 "10nF" N_0603 1711,-446.13 r270 bottom locked
C14 "4.7uF" N_0603 1649,-446.13 r270 bottom locked
C15 "10nF" N_0603 2319,-908 r0 top locked
C16 "1uF" N_0603 2319,-843 r0 top locked
C19 "NL" 0603 2045,-738 r0 top locked
C20 "NL" 0603 2045,-679 r0 top locked
C21 "NL" 0603 1859,-290.48 r90 bottom locked
C22 "NL" 0603 1800,-290.48 r90 bottom locked
C23 "10nF" N_0603 1681.95,-1677 r90 bottom locked
C24 "1uF" N_0603 1680,-1829 r270 bottom locked
C25 "10nF" N_0603 1650,-2351 r90 bottom locked
C26 "1uF" N_0603 1650.45,-2509 r270 bottom locked
C27 "10nF" N_0603 2168,-2991 r0 top locked
C28 "1uF" N_0603 2168,-3056 r0 top locked
C29 "10nF" N_0603 1036,-1113 r90 top locked
C30 "1uF" N_0603 1102,-1113 r90 top locked
CN7 "2X10_ML" 2X10-HEADER 2590,-640 r270 top locked
CN8 "2X8_ML" 2X8-HEADER 790,-900 r270 top locked
CN9 "2X15ML" 2X15-HEADER 790,-2150 r270 top locked
CN10 "2X17ML" 2X17-HEADER 2590,-1950 r270 top locked
CN11 "HDR2X35" 2X15X2-HEADER_CUSTOM 490,-1850 r270 bottom locked
CN12 "HDR2X35" 2X15X2-HEADER_CUSTOM 2890,-1851 r270 bottom locked
D0 "TP" "TEST POINT" 3170,-802 r90 top locked
D1 "TP" "TEST POINT" 3170,-902 r90 top locked
D2 "TP" "TEST POINT" 225,-2700 r90 top locked
D3 "TP" "TEST POINT" 225,-2900 r90 top locked
D4 "TP" "TEST POINT" 3170,-2302 r90 top locked
D5 "TP" "TEST POINT" 3170,-2002 r90 top locked
D6 "TP" "TEST POINT" 3170,-1202 r0 top locked
D7 "TP" "TEST POINT" 3170,-2502 r0 top locked
D8 "TP" "TEST POINT" 3170,-1302 r0 top locked
D9 "TP" "TEST POINT" 3170,-2602 r0 top locked
D10 "TP" "TEST POINT" 3170,-1602 r0 top locked
D11 "TP" "TEST POINT" 3170,-2702 r0 top locked
D12 "TP" "TEST POINT" 3170,-2802 r0 top locked
D13 "TP" "TEST POINT" 3170,-702 r0 top locked
D14 "TP" "TEST POINT" 225,-3550 r0 top locked
D15 "TP" "TEST POINT" 3170,-3202 r0 top locked
GND2 "GND" "TEST POINT" 2261,-1381 r90 top locked
GND3 "GND" "TEST POINT" 2288,-2851 r90 top locked
GND4 "GND" "TEST POINT" 225,-3650 r90 top locked
GND5 "GND" "TEST POINT" 225,-1200 r90 top locked
IC4 "CY14B101LA/NA_54PIN_TSOPX16" 54PIN_TSOP_SOCKET_CUSTOM 1681,-2090 r90 top locked
IOREF "TP" "TEST POINT" 225,-601 r90 top locked
JP2 "3PIN_JUMPER" "1X3 MALE HEADER WITH SHUNT_071513" 1462,-701 r0 top locked
JP4 "3PIN_JUMPER" "1X3 MALE HEADER WITH SHUNT_071513" 1002,-3037 r90 top locked
JP5 "4PIN_JUMPER" 1X4_HDR 1181,-1358 r0 top locked
JP6 "3PIN_JUMPER" "1X3 MALE HEADER WITH SHUNT_071513" 2131,-936 r270 top locked
JP12 "3.3V ENABLE" "1X2 HEADER WITH SHUNT_051914" 1464.35,-102.65 r270 top locked
L1 "BLM18SG121TN1D" 0603 1916,-686 r90 top locked
L2 "BLM18SG121TN1D" 0603 1899,-396 r90 top locked
LED2 "RED" "LED 0805 GREEN_032906" 2232,-172.78 r270 top locked
MRAM_CEb "TESTPOINT" "TEST POINT" 225,-1500 r90 top locked
MRAM_LBb "TESTPOINT" "TEST POINT" 3170,-3302 r90 top locked
MRAM_OEb "TP" "TEST POINT" 225,-1700 r90 top locked
MRAM_OEb_ALT "TESTPOINT" "TEST POINT" 3170,-1502 r90 top locked
MRAM_SEb "TESTPOINT" "TEST POINT" 225,-2400 r90 top locked
MRAM_UBb "TESTPOINT" "TEST POINT" 3170,-3502 r90 top locked
MRAM_WEb "TESTPOINT" "TEST POINT" 225,-1600 r90 top locked
OE_BUFb "TP" "TEST POINT" 3170,-3102 r90 top locked
OE_DFFb "TP" "TEST POINT" 225,-2001 r90 top locked
R1 "39 1%" N_0603 2747,-2102 r180 top
R2 "DNI" N_0402 1302.95,-1719 r270 bottom locked
R3 "DNI" N_0402 1268.95,-1792 r90 bottom locked
R4 "39 1%" N_0603 635,-2300 r0 top locked
R5 "DNI" N_0402 1303,-2208 r270 bottom locked
R6 "DNI" N_0402 1273,-2280 r90 bottom locked
R7 "39 1%" N_0603 636,-2100.89 r0 top locked
R8 "DNI" N_0402 1272,-2459.55 r90 bottom locked
R9 "DNI" N_0402 1240.45,-2387 r270 bottom locked
R10 "100K" N_0402 1837,-1971 r90 bottom locked
R11 "DNI" N_0402 1866,-1899 r270 bottom locked
R12 "2K" N_0603 2232,-333.78 r270 top locked
R13 "0" N_0603 1938,-169 r90 top locked
R14 "105K, 1%" N_0603 1819,-397 r270 top locked
R15 "30.9K, 1%" N_0603 1910.15,-264 r180 top locked
R16 "0" N_0603 1671,-204 r180 top locked
R17 "28.7K, 1%" N_0603 1819,-234 r270 top locked
R18 "39 1%" N_0603 334,-2751 r180 top locked
R19 "DNI" N_0402 1335.45,-2459 r90 bottom locked
R20 "DNI" N_0402 1304.45,-2387 r270 bottom locked
R21 "39 1%" N_0603 333,-2651 r0 top locked
R22 "DNI" N_0402 1366,-2208 r270 bottom locked
R23 "DNI" N_0402 1339,-2280 r90 bottom locked
R24 "39 1%" N_0603 336,-2500 r0 top locked
R25 "DNI" N_0402 1398.45,-2459 r90 bottom locked
R26 "DNI" N_0402 1371.45,-2387 r270 bottom locked
R27 "39 1%" N_0603 3046,-2951 r180 top locked
R28 "DNI" N_0402 1429,-2208 r270 bottom locked
R29 "DNI" N_0402 1401,-2280 r90 bottom locked
R30 "39 1%" N_0603 3046,-1951 r180 top locked
R31 "DNI" N_0402 1461.45,-2459 r90 bottom locked
R32 "DNI" N_0402 1434.45,-2387 r270 bottom locked
R33 "39 1%" N_0603 2740,-890 r180 top
R34 "DNI" N_0402 1524.45,-2459 r90 bottom locked
R35 "DNI" N_0402 1496.45,-2387 r270 bottom locked
R36 "39 1%" N_0603 2733,-990 r180 top locked
R37 "DNI" N_0402 1554,-2208 r270 bottom locked
R38 "DNI" N_0402 1529,-2280 r90 bottom locked
R39 "39 1%" N_0603 639,-2650 r0 top
R40 "DNI" N_0402 1587.45,-2459 r90 bottom locked
R41 "DNI" N_0402 1560.45,-2387 r270 bottom locked
R42 "39 1%" N_0603 640,-2751 r180 top
R43 "DNI" N_0402 1619,-2208 r270 bottom locked
R44 "DNI" N_0402 1592,-2280 r90 bottom locked
R45 "39 1%" N_0603 3046,-2251 r180 top locked
R46 "DNI" N_0402 1713.45,-2459 r90 bottom locked
R47 "DNI" N_0402 1740.45,-2387 r270 bottom locked
R48 "39 1%" N_0603 2744,-2002 r180 top
R49 "DNI" N_0402 1745,-2208 r270 bottom locked
R50 "DNI" N_0402 1771,-2280 r90 bottom locked
R51 "39 1%" N_0603 2741,-1351 r180 top
R52 "DNI" N_0402 1776.45,-2460 r90 bottom locked
R53 "DNI" N_0402 1806.45,-2388 r270 bottom locked
R54 "39 1%" N_0603 2744,-2392 r180 top
R55 "DNI" N_0402 1806,-2208 r270 bottom locked
R56 "DNI" N_0402 1833,-2280 r90 bottom locked
R57 "39 1%" N_0603 3046,-1851 r180 top locked
R58 "DNI" N_0402 1870,-2208 r270 bottom locked
R59 "DNI" N_0402 1898,-2281 r90 bottom locked
R60 "39 1%" N_0603 2744,-1090 r180 top
R61 "DNI" N_0402 1901.45,-2460 r90 bottom locked
R62 "DNI" N_0402 1930.45,-2388 r270 bottom locked
R63 "39 1%" N_0603 2740,-1250 r180 top
R64 "DNI" N_0402 1933,-2209 r270 bottom locked
R65 "DNI" N_0402 1961,-2281 r90 bottom locked
R66 "39 1%" N_0603 2741,-1550 r180 top
R67 "DNI" N_0402 1966.45,-2460 r90 bottom locked
R68 "DNI" N_0402 1998.45,-2388 r270 bottom locked
R69 "39 1%" N_0603 2740,-1750 r180 top
R70 "DNI" N_0402 1996,-2209 r270 bottom locked
R71 "DNI" N_0402 2031,-2281 r90 bottom locked
R72 "39 1%" N_0603 2743,-2198 r180 top
R73 "DNI" N_0402 1335,-1970 r90 bottom locked
R74 "DNI" N_0402 1309,-1898 r270 bottom locked
R75 "39 1%" N_0603 2744,-2306 r180 top
R76 "DNI" N_0402 1366.95,-1719 r270 bottom locked
R77 "DNI" N_0402 1337.95,-1792 r90 bottom locked
R78 "39 1%" N_0603 3046,-3451 r180 top locked
R79 "DNI" N_0402 1397,-1970 r90 bottom locked
R80 "DNI" N_0402 1371,-1898 r270 bottom locked
R81 "39 1%" N_0603 2739,-3351 r0 top locked
R82 "DNI" N_0402 1524,-1970 r90 bottom locked
R83 "DNI" N_0402 1499,-1898 r270 bottom locked
R84 "39 1%" N_0603 336,-3550 r0 top locked
R85 "DNI" N_0402 1554.95,-1720 r270 bottom locked
R86 "DNI" N_0402 1525.95,-1792 r90 bottom locked
R87 "39 1%" N_0603 3035,-580 r90 top locked
R88 "DNI" N_0402 1588,-1973 r90 bottom locked
R89 "DNI" N_0402 1558,-1898 r270 bottom locked
R90 "39 1%" N_0603 2741,-2649 r180 top
R91 "DNI" N_0402 1618.95,-1720 r270 bottom locked
R92 "DNI" N_0402 1589.95,-1792 r90 bottom locked
R93 "39 1%" N_0603 2741,-2551 r180 top
R94 "DNI" N_0402 1712,-1971 r90 bottom locked
R95 "DNI" N_0402 1743,-1899 r270 bottom locked
R96 "39 1%" N_0603 2742,-1650 r180 top
R97 "DNI" N_0402 1744.95,-1720 r270 bottom locked
R98 "DNI" N_0402 1767.95,-1793 r90 bottom locked
R99 "39 1%" N_0603 2744,-2457 r180 top
R100 "DNI" N_0402 1776,-1971 r90 bottom locked
R101 "DNI" N_0402 1804,-1899 r270 bottom locked
R102 "39 1%" N_0603 2742,-1451 r180 top
R103 "DNI" N_0402 1805.95,-1720 r270 bottom locked
R104 "DNI" N_0402 1830.95,-1793 r90 bottom locked
R105 "39 1%" N_0603 2739,-3551 r0 top locked
R106 "DNI" N_0402 1870.95,-1720 r270 bottom locked
R107 "DNI" N_0402 1894.95,-1793 r90 bottom locked
R108 "39 1%" N_0603 643,-1299 r0 top locked
R109 "DNI" N_0402 1902,-1971 r90 bottom locked
R110 "DNI" N_0402 1927,-1899 r270 bottom locked
R111 "39 1%" N_0603 643,-1201 r0 top locked
R112 "DNI" N_0402 1933.95,-1720 r270 bottom locked
R113 "DNI" N_0402 1962.95,-1793 r90 bottom locked
R114 "39 1%" N_0603 650,-2952 r0 top locked
R115 "DNI" N_0402 1965,-1970 r90 bottom locked
R116 "DNI" N_0402 1998.43,-1899 r270 bottom locked
R117 "39 1%" N_0603 638,-2852 r0 top
R118 "DNI" N_0402 1995.95,-1720 r270 bottom locked
R119 "DNI" N_0402 2027.95,-1793 r90 bottom locked
R120 "39 1%" N_0603 643,-1800 r0 top locked
R121 "100K" N_0402 1428.95,-1720 r270 bottom locked
R122 "DNI" N_0402 1401.95,-1792 r90 bottom locked
R123 "39 1%" N_0603 3046,-3551 r180 top locked
R124 "100K" N_0402 1839.45,-2460 r90 bottom locked
R125 "DNI" N_0402 1866.45,-2388 r270 bottom locked
R126 "39 1%" N_0603 2739,-3451 r0 top locked
R127 "100K" N_0402 1461,-1970 r90 bottom locked
R128 "DNI" N_0402 1431,-1898 r270 bottom locked
R129 "39 1%" N_0603 638,-2401 r0 top locked
R130 "100K" N_0402 1491,-2208 r270 bottom locked
R131 "DNI" N_0402 1464.35,-2280 r90 bottom locked
R132 "39 1%" N_0603 640,-1601 r0 top locked
R133 "100K" N_0402 1492.95,-1720 r270 bottom locked
R134 "DNI" N_0402 1462.95,-1792 r90 bottom locked
R135 "39 1%" N_0603 638,-1504 r0 top locked
R136 "39 1%" N_0603 636,-2200 r0 top locked
R137 "DNI" N_0402 1272,-1970 r90 bottom locked
R138 "DNI" N_0402 1239,-1898 r270 bottom locked
R140 "0" N_0603 1559,-172 r90 top locked
R141 "DNI" N_0603 2121,-2463 r180 bottom locked
R142 "0" N_0603 1089,-2886 r270 bottom locked
R143 "0" N_0603 2208.5,-1083.5 r90 bottom locked
R144 "0" N_0603 1518,-788 r180 bottom locked
RSTB "TP" "TEST POINT" 225,-700 r90 top locked
SHDN1 "TP" "TEST POINT" 1623.5,-821.5 r180 top locked
TP1 "TP" "TEST POINT" 2056,-2803 r0 top locked (schematic designator NC1)
TP2 "TP" "TEST POINT" 2133.95,-2851 r0 top locked (schematic designator VINTH)
TP3 "TP" "TEST POINT" 2212,-2802 r0 top locked (schematic designator V18)
TP4 "TP" "TEST POINT" 2124,-1381 r0 top locked (schematic designator VPP)
TP5 "TP" "TEST POINT" 2058.95,-1291 r0 top locked (schematic designator VDD)
TP6 "TP" "TEST POINT" 2009,-1382 r0 top locked (schematic designator NC2)
U1 "SN74LVC574A" R-PDSO-G20 1813.24,-1017.34 r180 top locked
U2 "SN74LVC574A" R-PDSO-G20 1444.76,-3179.66 r0 top locked
U3 "MCP1825T-ADJE/DC" "SOT223-6 REGULATOR_010419" 1553,-476.13 r90 top locked
U4 "SN74LVTH244A" DB0020A 1338.29,-1017.34 r180 top locked
U5 "SN74LVTH244A" DB0020A 1922.21,-3182.16 r0 top locked
U6 "SN74LVC2G06" SOT-23 2289,-1045 r90 top locked
VCC "TP" "TEST POINT" 2007,-344 r90 top locked
VIN "TP" "TEST POINT" 2012,-573 r90 top locked
VOUT "TP" "TEST POINT" 2007,-467 r180 top locked

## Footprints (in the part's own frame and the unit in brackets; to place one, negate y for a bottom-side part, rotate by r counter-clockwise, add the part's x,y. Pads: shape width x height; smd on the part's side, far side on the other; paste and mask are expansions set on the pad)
"1X2 HEADER WITH SHUNT_051914" [mil] "TH"
  rect 62x62 hole 35: 1(0,0)
  round 62 hole 35: 2(100,0)
  silkscreen extent -50,-50 155,50, body extent -50,-50 150,50, height 332
"1X3 MALE HEADER WITH SHUNT_071513" [mil] "TH"
  rect 62x62 hole 35: 1(0,0)
  round 62 hole 35: 2(100,0) 3(200,0)
  silkscreen extent -60,-55 260,55, body extent -46,-49 254,49, height 323
1X4_HDR [mil] "TH"
  rect 62x62 hole 35: 1(-150,0)
  round 62 hole 35: 2(-50,0) 3(50,0) 4(-50,100)
  silkscreen extent -210,-55 110,150
2X8-HEADER [mil] "TH"
  rect 62x62 hole 40: 1(-350,-50)
  round 62 hole 40: 2(-350,50) 3(-250,-50) 4(-250,50) 5(-150,-50) 6(-150,50) 7(-50,-50) 8(-50,50) 9(50,-50) 10(50,50) 11(150,-50) 12(150,50) 13(250,-50) 14(250,50) 15(350,-50) 16(350,50)
  silkscreen extent -400,-100 400,100, body extent -400,-100 400,100, height 335
2X10-HEADER [mil] "TH"
  rect 62x62 hole 40: 1(-450,-50)
  round 62 hole 40: 2(-450,50) 3(-350,-50) 4(-350,50) 5(-250,-50) 6(-250,50) 7(-150,-50) 8(-150,50) 9(-50,-50) 10(-50,50) 11(50,-50) 12(50,50) 13(150,-50) 14(150,50) 15(250,-50) 16(250,50) 17(350,-50) 18(350,50) 19(450,-50) 20(450,50)
  body extent -500,-100 500,100, height 335
2X15-HEADER [mil] "TH"
  rect 62x62 hole 40: 1(-700,-50)
  round 62 hole 40: 2(-700,50) 3(-600,-50) 4(-600,50) 5(-500,-50) 6(-500,50) 7(-400,-50) 8(-400,50) 9(-300,-50) 10(-300,50) 11(-200,-50) 12(-200,50) 13(-100,-50) 14(-100,50) 15(0,-50) 16(0,50) 17(100,-50) 18(100,50) 19(200,-50) 20(200,50) 21(300,-50) 22(300,50) 23(400,-50) 24(400,50) 25(500,-50) 26(500,50) 27(600,-50) 28(600,50) 29(700,-50) 30(700,50)
  silkscreen extent -750,-100 -750,100, body extent -750,-100 750,100, height 335
2X15X2-HEADER_CUSTOM [mil] "TH"
  rect 62x62 hole 40: 1(-1700,50)
  round 62 hole 40: 2(-1700,-50) 3(-1600,50) 4(-1600,-50) 5(-1500,50) 6(-1500,-50) 7(-1400,50) 8(-1400,-50) 9(-1300,50) 10(-1300,-50) 11(-1200,50) 12(-1200,-50) 13(-1100,50) 14(-1100,-50) 15(-1000,50) 16(-1000,-50) 17(-900,50) 18(-900,-50) 19(-800,50) 20(-800,-50) 21(-700,50) 22(-700,-50) 23(-600,50) 24(-600,-50) 25(-500,50) 26(-500,-50) 27(-400,50) 28(-400,-50) 29(-300,50) 30(-300,-50) 31(-200,50) 32(-200,-50) 33(-100,50) 34(-100,-50) 35(0,50) 36(0,-50) 37(100,50) 38(100,-50) 39(200,50) 40(200,-50) 41(300,50) 42(300,-50) 43(400,50) 44(400,-50) 45(500,50) 46(500,-50) 47(600,50) 48(600,-50) 49(700,50) 50(700,-50) 51(800,50) 52(800,-50) 53(900,50) 54(900,-50) 55(1000,50) 56(1000,-50) 57(1100,50) 58(1100,-50) 59(1200,50) 60(1200,-50) 61(1300,50) 62(1300,-50) 63(1400,50) 64(1400,-50) 65(1500,50) 66(1500,-50) 67(1600,50) 68(1600,-50) 69(1700,50) 70(1700,-50)
  silkscreen extent -1775,-100 1750,100, body extent -1750,-100 1750,100, height 335
2X17-HEADER [mil] "TH"
  rect 62x62 hole 40: 1(-700,-50)
  round 62 hole 40: 2(-700,50) 3(-600,-50) 4(-600,50) 5(-500,-50) 6(-500,50) 7(-400,-50) 8(-400,50) 9(-300,-50) 10(-300,50) 11(-200,-50) 12(-200,50) 13(-100,-50) 14(-100,50) 15(0,-50) 16(0,50) 17(100,-50) 18(100,50) 19(200,-50) 20(200,50) 21(300,-50) 22(300,50) 23(400,-50) 24(400,50) 25(500,-50) 26(500,50) 27(600,-50) 28(600,50) 29(700,-50) 30(700,50) 31(800,-50) 32(800,50) 33(900,-50) 34(900,50)
  body extent -750,-100 950,100, height 335
54PIN_TSOP_SOCKET_CUSTOM [mil] "SM FP"
  rect 100x18 smd mask+1.5: 1(-245,409.45) 2(-245,377.95) 3(-245,346.46) 4(-245,314.96) 5(-245,283.46) 6(-245,251.97) 7(-245,220.47) 8(-245,188.98) 9(-245,157.48) 10(-245,125.98) 11(-245,94.49) 12(-245,62.99) 13(-245,31.5) 14(-245,0) 15(-245,-31.5) 16(-245,-62.99) 17(-245,-94.49) 18(-245,-125.98) 19(-245,-157.48) 20(-245,-188.98) 21(-245,-220.47) 22(-245,-251.97) 23(-245,-283.46) 24(-245,-314.96) 25(-245,-346.46) 26(-245,-377.95) 27(-245,-409.45) 28(245,-409.45) 29(245,-377.95) 30(245,-346.46) 31(245,-314.96) 32(245,-283.46) 33(245,-251.97) 34(245,-220.47) 35(245,-188.98) 36(245,-157.48) 37(245,-125.98) 38(245,-94.49) 39(245,-62.99) 40(245,-31.5) 41(245,0) 42(245,31.5) 43(245,62.99) 44(245,94.49) 45(245,125.98) 46(245,157.48) 47(245,188.98) 48(245,220.47) 49(245,251.97) 50(245,283.46) 51(245,314.96) 52(245,346.46) 53(245,377.95) 54(245,409.45)
  round 40 hole 63 unplated: GUIDEPIN_1.6NP(-406,505) GUIDEPIN_1.6NP(405,-505)
  round 50 on Mech2: ORIGIN(0,0)
  round 150 hole 90.55 unplated: ""(-506,-605) ""(-506,605) ""(505,605) ""(505,-605)
  Keep-Out Layer circle w5: c-406,505 r45
  Keep-Out Layer circle w5: c405,-505 r45
  silkscreen extent -626,-725 625,725
0603 [mil]
  rect 30x40 smd: 1(-30,0) 2(30,0)
  silkscreen extent -54,-29 54,29
DB0020A [mm]
  rect 1.85x0.45 smd mask+0.07: 1(-3.5,2.925) 2(-3.5,2.275) 3(-3.5,1.625) 4(-3.5,0.975) 5(-3.5,0.325) 6(-3.5,-0.325) 7(-3.5,-0.975) 8(-3.5,-1.625) 9(-3.5,-2.275) 10(-3.5,-2.925) 11(3.5,-2.925) 12(3.5,-2.275) 13(3.5,-1.625) 14(3.5,-0.975) 15(3.5,-0.325) 16(3.5,0.325) 17(3.5,0.975) 18(3.5,1.625) 19(3.5,2.275) 20(3.5,2.925)
  silkscreen extent -2.16,-3.56 2.16,4.01
"LED 0805 GREEN_032906" [mil] "SMT"
  rect 40x50 smd: A(33.46,0) C(-33.46,0)
  silkscreen extent -92,-45 70,45, body extent -41,-18 41,18, height 33
N_0402 [mil] "Chip Capacitor, Body 1.0x0.5mm, IPC High Density"
  rect 24x20 smd: 1(-18,0) 2(18,0)
  round 20 on Mech2: ""(0,0)
  silkscreen extent -36,-20 36,20, body extent -22,-12 22,12, height 51
N_0603 [mil]
  rect 38x40 smd: 1(-30,0) 2(30,0)
  silkscreen extent -61,-33 62,32, body extent -34,-16 32,16, height 22
R-PDSO-G20 [mm]
  rect 1.6x0.3 smd mask+0.07: 1(-2.8,2.925) 2(-2.8,2.275) 3(-2.8,1.625) 4(-2.8,0.975) 5(-2.8,0.325) 6(-2.8,-0.325) 7(-2.8,-0.975) 8(-2.8,-1.625) 9(-2.8,-2.275) 10(-2.8,-2.925) 11(2.8,-2.925) 12(2.8,-2.275) 13(2.8,-1.625) 14(2.8,-0.975) 15(2.8,-0.325) 16(2.8,0.325) 17(2.8,0.975) 18(2.8,1.625) 19(2.8,2.275) 20(2.8,2.925)
  silkscreen extent -1.65,-3.43 1.65,3.76
"SOT223-6 REGULATOR_010419" [mm] "SMT"
  rect 0.65x2 smd mask+0.05: 1(-2.54,-3) 2(-1.27,-3) 3(0,-3) 4(1.27,-3) 5(2.54,-3)
  rect 3.2x2 smd: 3(0,3)
  silkscreen extent -3.65,-4.32 3.65,4.35, body extent -3.27,-3.63 3.28,3.63, height 1.8
SOT-23 [mm]
  rrect50% 1.1x0.6 smd mask+0.07: 1(-1.3,1.27) 2(-1.3,0) 3(-1.3,-1.27) 4(1.3,-1.27) 5(1.3,0) 6(1.3,1.27)
  silkscreen extent -2.16,-1.91 2.16,1.91
"TEST POINT" [mil] "TH"
  round 60 hole 40: 1(0,0)
  silkscreen extent -40,-40 40,40

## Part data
+5V0 A0 A1 A2 A3 A4 A5 A6 A7 A8 A9 A10 A11 A12 A13 A14 A15 A16 A17 A18 A19 A20 A21 D0 D1 D2 D3 D4 D5 D6 D7 D8 D9 D10 D11 D12 D13 D14 D15 GND2 GND3 GND4 GND5 IOREF MRAM_CEb MRAM_LBb MRAM_OEb MRAM_OEb_ALT MRAM_SEb MRAM_UBb MRAM_WEb OE_BUFb OE_DFFb RSTB SHDN1 TP1 TP2 TP3 TP4 TP5 TP6 VCC VIN VOUT: library part "TEST POINT 1"
C7 C8 C9 C10 C11 C12 C13 C14 C15 C16 C23 C24 C25 C26 C27 C28 C29 C30: library part C-USC0603, "<B>CAPACITOR</B>, American symbol"
C19 C20 C21 C22: library part C-USC0805, "<B>CAPACITOR</B>, American symbol"
JP2 JP4 JP5 JP6: "DNI"
JP12: library part PINHD-1X2, "DNI"
L1 L2: library part FB
LED2: library part LEDCHIP-LED0805, "<b>LED</b><p> / <u>OSRAM</u>:<br> /  / - <u>CHIPLED</u><br> / LG R971, LG N971, LY N971, LG Q971, LY Q971, LO R971, LY R971 / LH N974, LH R974<br> / LS Q976, LO Q976, LY Q976<br> / LO Q996<br> /  / - <u>Hyper CHIPLED</u><br> / LW Q18S<br> / LB Q993, LB Q99A, LB R99A<br> /  / - <u>SideLED</u><br> / LS A670, LO A670, LY A670, LG A670, LP A670<br> / LB A673, LV A673, LT A673, LW A673<br> / LH A674<br> / LY A675<br> / LS A676, LA A676, LO A676, LY A676, LW A676<br> / LS A679, LY A679, LG A679<br> /  / -  <u>Hyper Micro SIDELED®</u><br> / LS Y876, LA Y876, LO Y876, LY Y876<br> / LT Y87S<br> /  / - <u>SmartLED</u><br> / LW L88C, LW L88S<br> / LB L89C, LB L89S, LG L890<br> / LS L89K, LO L89K, LY L89K<br> / LS L896, LA L896, LO L896, LY L896<br> /  / - <u>TOPLED</u><br> / LS T670, LO T670, LY T670, LG T670, LP T670<br> / LSG T670, LSP T670, LSY T670, LOP T670, LYG T670<br> / LG T671, LOG T671, LSG T671<br> / LB T673, LV T673, LT T673, LW T673<br> / LH T674<br> / LS T676, LA T676, LO T676, LY T676, LB T676, LH T676, LSB T676, LW T676<br> / LB T67C, LV T67C, LT T67C, LS T67K, LO T67K, LY T67K, LW E67C<br> / LS E67B, LA E67B, LO E67B, LY E67B, LB E67C, LV E67C, LT E67C<br> / LW T67C<br> / LS T679, LY T679, LG T679<br> / LS T770, LO T770, LY T770, LG T770, LP T770<br> / LB T773, LV T773, LT T773, LW T773<br> / LH T774<br> / LS E675, LA E675, LY E675, LS T675<br> / LS T776, LA T776, LO T776, LY T776, LB T776<br> / LHGB T686<br> / LT T68C, LB T68C<br> /  / - <u>Hyper Mini TOPLED®</u><br> / LB M676<br> /  / - <u>Mini TOPLED Santana®</u><br> / LG M470<br> / LS M47K, LO M47K, LY M47K / <p> / Source: http://www.osram.convergy.de<p> /  / <u>LUXEON:</u><br> / - <u>LUMILED®</u><br> / LXK2-PW12-R00, LXK2-PW12-S00, LXK2-PW14-U00, LXK2-PW14-V00<br> / LXK2-PM12-R00, LXK2-PM12-S00, LXK2-PM14-U00<br> / LXK2-PE12-Q00, LXK2-PE12-R00, LXK2-PE12-S00, LXK2-PE14-T00, LXK2-PE14-U00<br> / LXK2-PB12-K00, LXK2-PB12-L00, LXK2-PB12-M00, LXK2-PB14-N00, LXK2-PB14-P00, LXK2-PB14-Q00<br> / LXK2-PR12-L00, LXK2-PR12-M00, LXK2-PR14-Q00, LXK2-PR14-R00<br> / LXK2-PD12-Q00, LXK2-PD12-R00, LXK2-PD12-S00<br> / LXK2-PH12-R00, LXK2-PH12-S00<br> / LXK2-PL12-P00, LXK2-PL12-Q00, LXK2-PL12-R00 / <p> / Source: www.luxeon.com<p> /  / <u>KINGBRIGHT:</U><p> / KA-3528ASYC<br> / Source: www.kingbright.com"
R1 R4 R7 R12 R13 R14 R15 R16 R17 R18 R21 R24 R27 R30 R33 R36 R39 R42 R45 R48 R51 R54 R57 R60 R63 R66 R69 R72 R75 R78 R81 R84 R87 R90 R93 R96 R99 R102 R105 R108 R111 R114 R117 R120 R123 R126 R129 R132 R135 R136 R140 R141 R142 R143 R144: library part R-US_R0603, "<B>RESISTOR</B>, American symbol"
R2 R3 R5 R6 R8 R9 R10 R11 R19 R20 R22 R23 R25 R26 R28 R29 R31 R32 R34 R35 R37 R38 R40 R41 R43 R44 R46 R47 R49 R50 R52 R53 R55 R56 R58 R59 R61 R62 R64 R65 R67 R68 R70 R71 R73 R74 R76 R77 R79 R80 R82 R83 R85 R86 R88 R89 R91 R92 R94 R95 R97 R98 R100 R101 R103 R104 R106 R107 R109 R110 R112 R113 R115 R116 R118 R119 R121 R122 R124 R125 R127 R128 R130 R131 R133 R134 R137 R138: library part R-US_R0603

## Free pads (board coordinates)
  round 60 hole 40: 1(225,-3199) 1(225,-403) 1(3168,-605) 1(3168,-505) 1(3170,-2901)
  round 20 on Mech16: 1(440,-3650) 1(440,-3550) 1(440,-3450) 1(440,-3350) 1(440,-3250) 1(440,-2950) 1(440,-2850) 1(440,-2750) 1(440,-2650) 1(440,-2550) 1(440,-2450) 1(440,-2350) 1(440,-2250) 1(440,-2150) 1(440,-2050) 1(440,-1950) 1(440,-1850) 1(440,-1750) 1(440,-1650) 1(440,-1550) 1(440,-1450) 1(440,-1350) 1(440,-1250) 1(440,-1150) 1(440,-1050) 1(440,-950) 1(440,-850) 1(440,-750) 1(440,-650) 1(440,-550) 1(440,-450) 1(440,-350) 1(440,-250) 1(440,-150) 1(540,-3650) 1(540,-3550) 1(540,-3450) 1(540,-3350) 1(540,-3250) 1(540,-2950) 1(540,-2850) 1(540,-2750) 1(540,-2650) 1(540,-2550) 1(540,-2450) 1(540,-2350) 1(540,-2250) 1(540,-2150) 1(540,-2050) 1(540,-1950) 1(540,-1850) 1(540,-1750) 1(540,-1650) 1(540,-1550) 1(540,-1450) 1(540,-1350) 1(540,-1250) 1(540,-1150) 1(540,-1050) 1(540,-950) 1(540,-850) 1(540,-750) 1(540,-650) 1(540,-550) 1(540,-450) 1(540,-350) 1(540,-250) 1(540,-150) 1(740,-2850) 1(740,-2750) 1(740,-2650) 1(740,-2550) 1(740,-2450) 1(740,-2350) 1(740,-2250) 1(740,-2150) 1(740,-2050) 1(740,-1950) 1(740,-1850) 1(740,-1750) 1(740,-1650) 1(740,-1550) 1(740,-1450) 1(740,-1250) 1(740,-1150) 1(740,-1050) 1(740,-950) 1(740,-850) 1(740,-750) 1(740,-650) 1(740,-550) 1(840,-2850) 1(840,-2750) 1(840,-2650) 1(840,-2550) 1(840,-2450) 1(840,-2350) 1(840,-2250) 1(840,-2150) 1(840,-2050) 1(840,-1950) 1(840,-1850) 1(840,-1750) 1(840,-1650) 1(840,-1550) 1(840,-1450) 1(840,-1250) 1(840,-1150) 1(840,-1050) 1(840,-950) 1(840,-850) 1(840,-750) 1(840,-650) 1(840,-550) 1(2540,-1450) 1(2540,-1350) 1(2540,-1250) 1(2540,-1090) 1(2540,-990) 1(2540,-890) 1(2540,-790) 1(2540,-690) 1(2540,-590) 1(2540,-490) 1(2540,-390) 1(2540,-290) 1(2540,-190) 1(2640,-1450) 1(2640,-1350) 1(2640,-1250) 1(2640,-1090) 1(2640,-990) 1(2640,-890) 1(2640,-790) 1(2640,-690) 1(2640,-590) 1(2640,-490) 1(2640,-390) 1(2640,-290) 1(2640,-190) 1(2840,-3651) 1(2840,-3551) 1(2840,-3451) 1(2840,-3351) 1(2840,-3251) 1(2840,-3151) 1(2840,-3051) 1(2840,-2951) 1(2840,-2851) 1(2840,-2751) 1(2840,-2651) 1(2840,-2551) 1(2840,-2451) 1(2840,-2351) 1(2840,-2251) 1(2840,-2151) 1(2840,-2051) 1(2840,-1951) 1(2840,-1851) 1(2840,-1751) 1(2840,-1651) 1(2840,-1551) 1(2840,-1451) 1(2840,-1351) 1(2840,-1251) 1(2840,-1151) 1(2840,-1051) 1(2840,-951) 1(2840,-851) 1(2840,-751) 1(2840,-651) 1(2840,-551) 1(2840,-451) 1(2840,-351) 1(2840,-251) 1(2840,-151) 1(2940,-3651) 1(2940,-3551) 1(2940,-3451) 1(2940,-3351) 1(2940,-3251) 1(2940,-3151) 1(2940,-3051) 1(2940,-2951) 1(2940,-2851) 1(2940,-2751) 1(2940,-2651) 1(2940,-2551) 1(2940,-2451) 1(2940,-2351) 1(2940,-2251) 1(2940,-2151) 1(2940,-2051) 1(2940,-1951) 1(2940,-1851) 1(2940,-1751) 1(2940,-1651) 1(2940,-1551) 1(2940,-1451) 1(2940,-1351) 1(2940,-1251) 1(2940,-1151) 1(2940,-1051) 1(2940,-951) 1(2940,-851) 1(2940,-751) 1(2940,-651) 1(2940,-551) 1(2940,-451) 1(2940,-351) 1(2940,-251) 1(2940,-151)
  round 200 / inner round 150 / far side round 200 hole 126 mask+3: ""(150,-150) ""(150,-3850) ""(3250,-150) ""(3250,-3850)
  round 50 smd: ""(381,-3911) ""(857,-199) ""(3052,-3730)
  round 50 smd far side: ""(398,-3892) ""(3071,-229) ""(3117,-3724)
  round 60 on Mech9: ""(740,-1450) ""(740,-550)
